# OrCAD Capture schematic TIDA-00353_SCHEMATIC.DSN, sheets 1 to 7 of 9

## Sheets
1 PAGE6 CLOCK_TRANSFORMERS: size B; title: ADC16DX370_LM97937EVM; rev: A; note: CLOCK_TRANSFORMERS
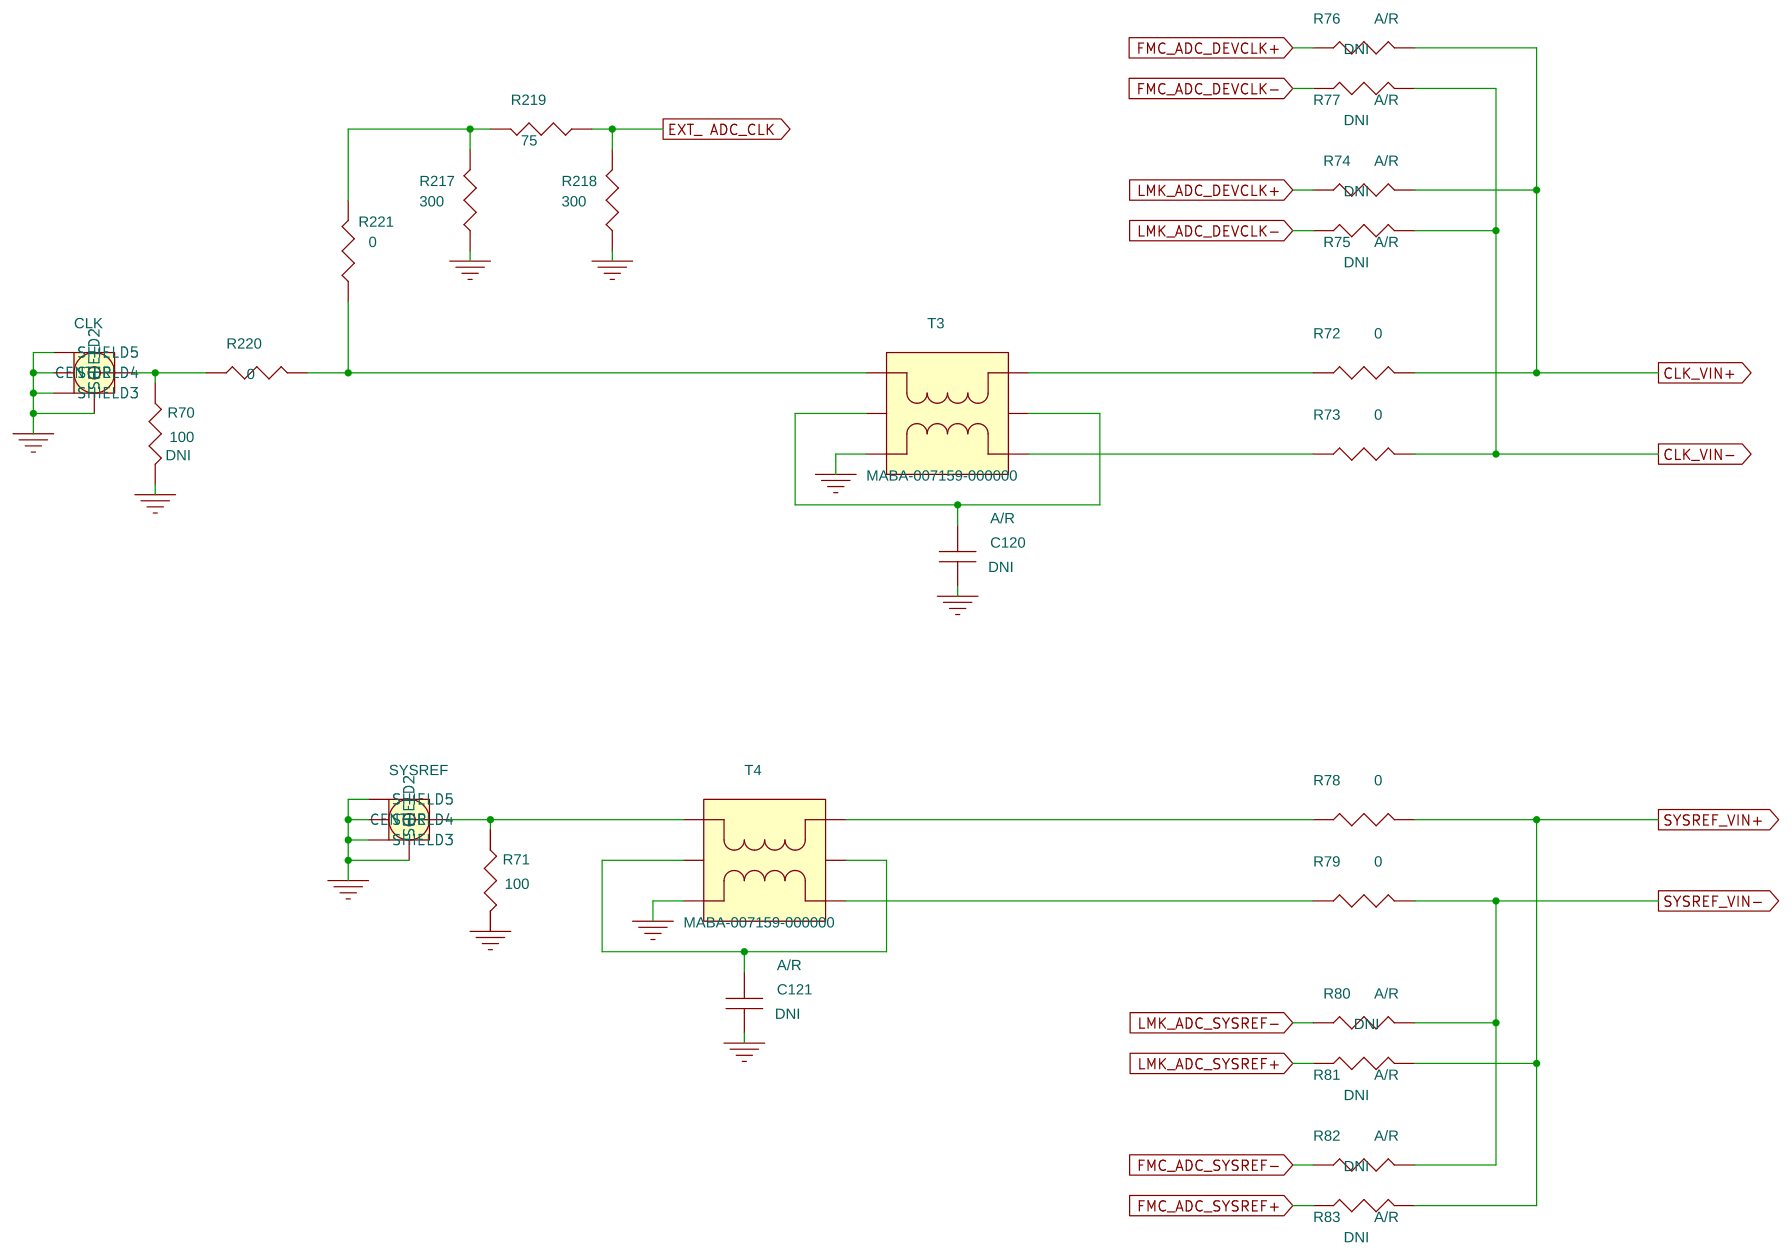
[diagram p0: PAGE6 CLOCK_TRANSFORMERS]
2 PAGE3 BPF: size B; note: BANDPASS_FILTERS
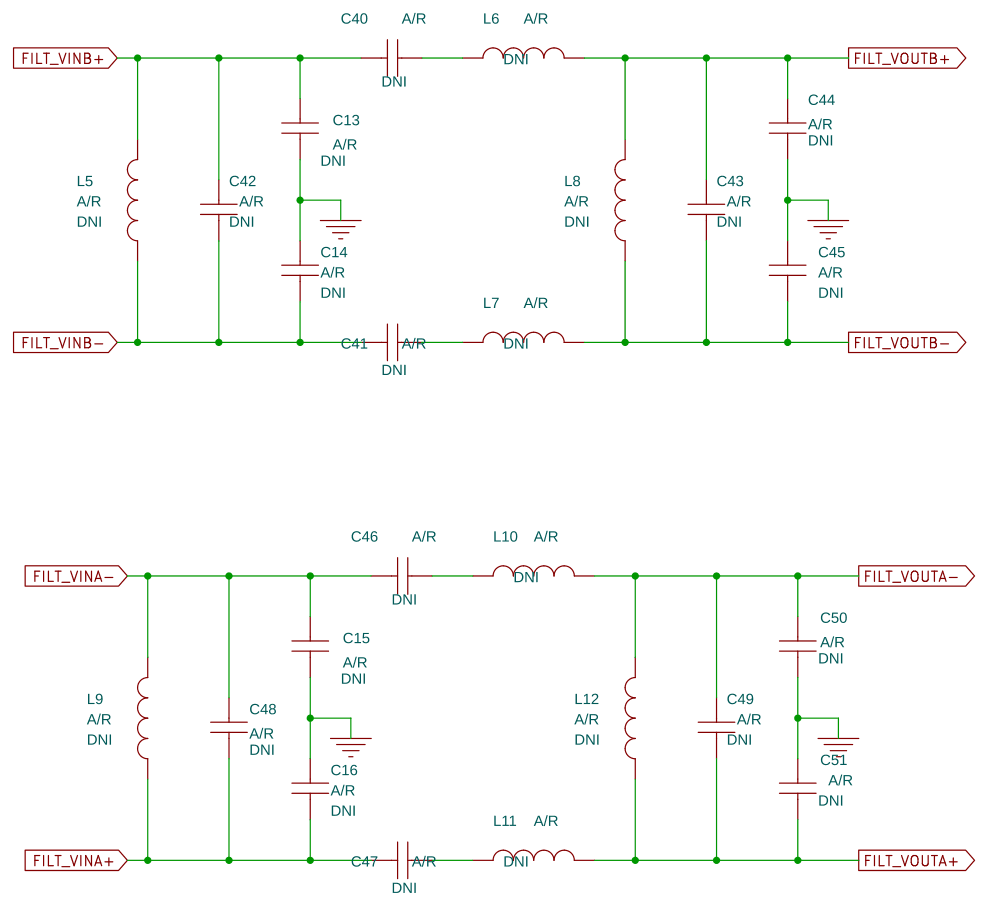
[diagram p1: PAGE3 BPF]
3 PAGE1 INPUT_TRANSFORMERS: size B
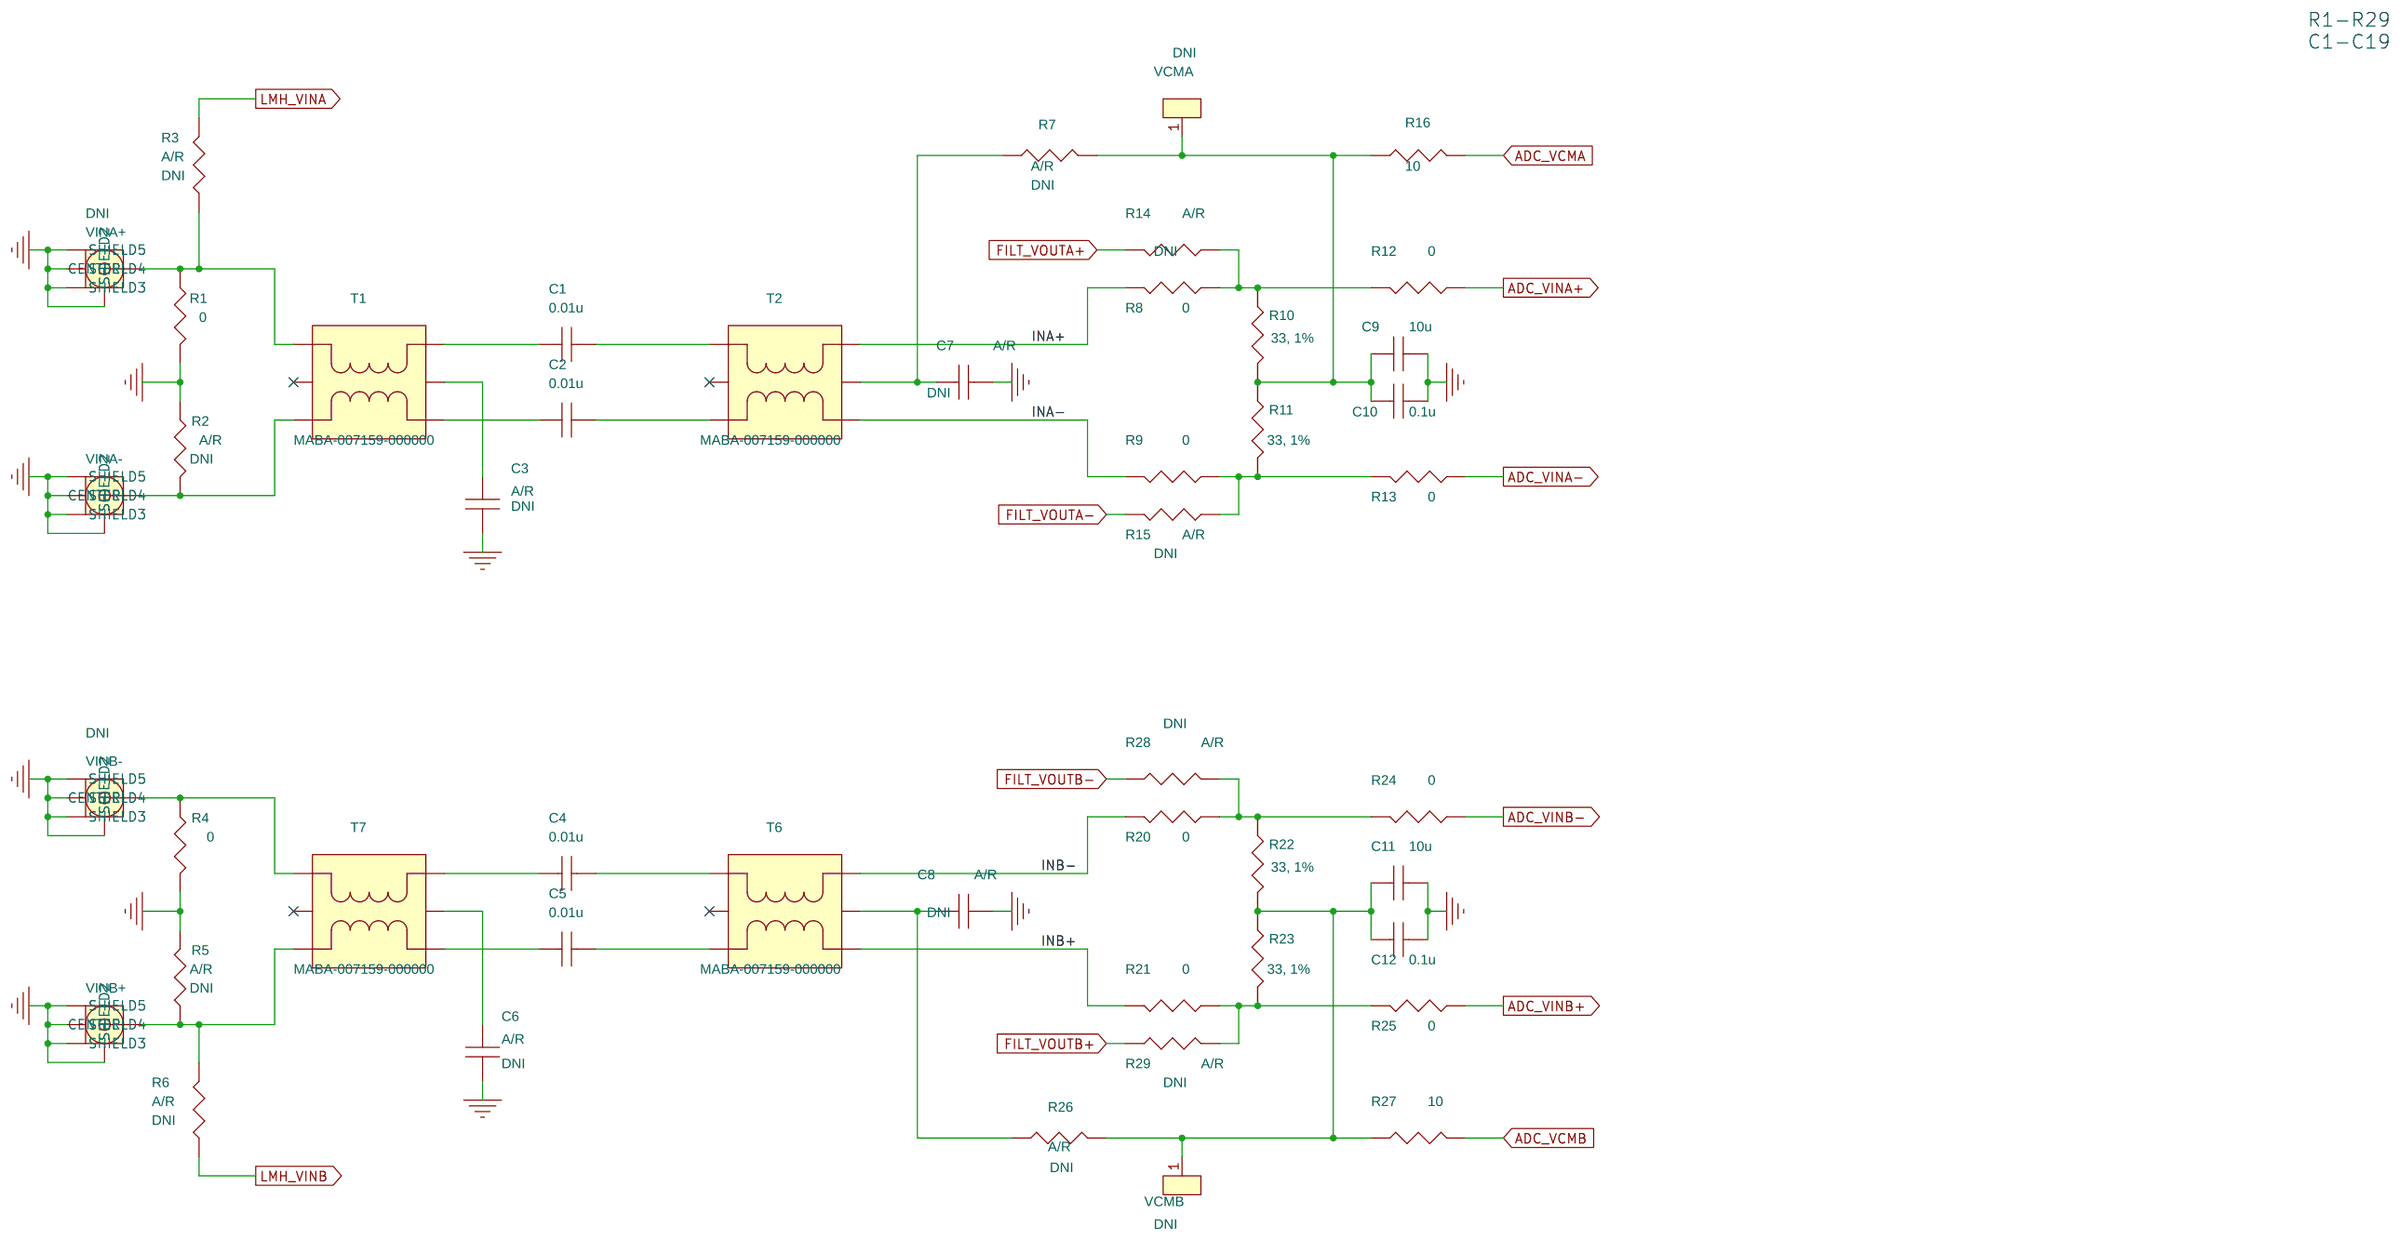
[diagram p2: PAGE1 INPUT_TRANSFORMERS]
4 PAGE2 LMH: size B; note: LMH
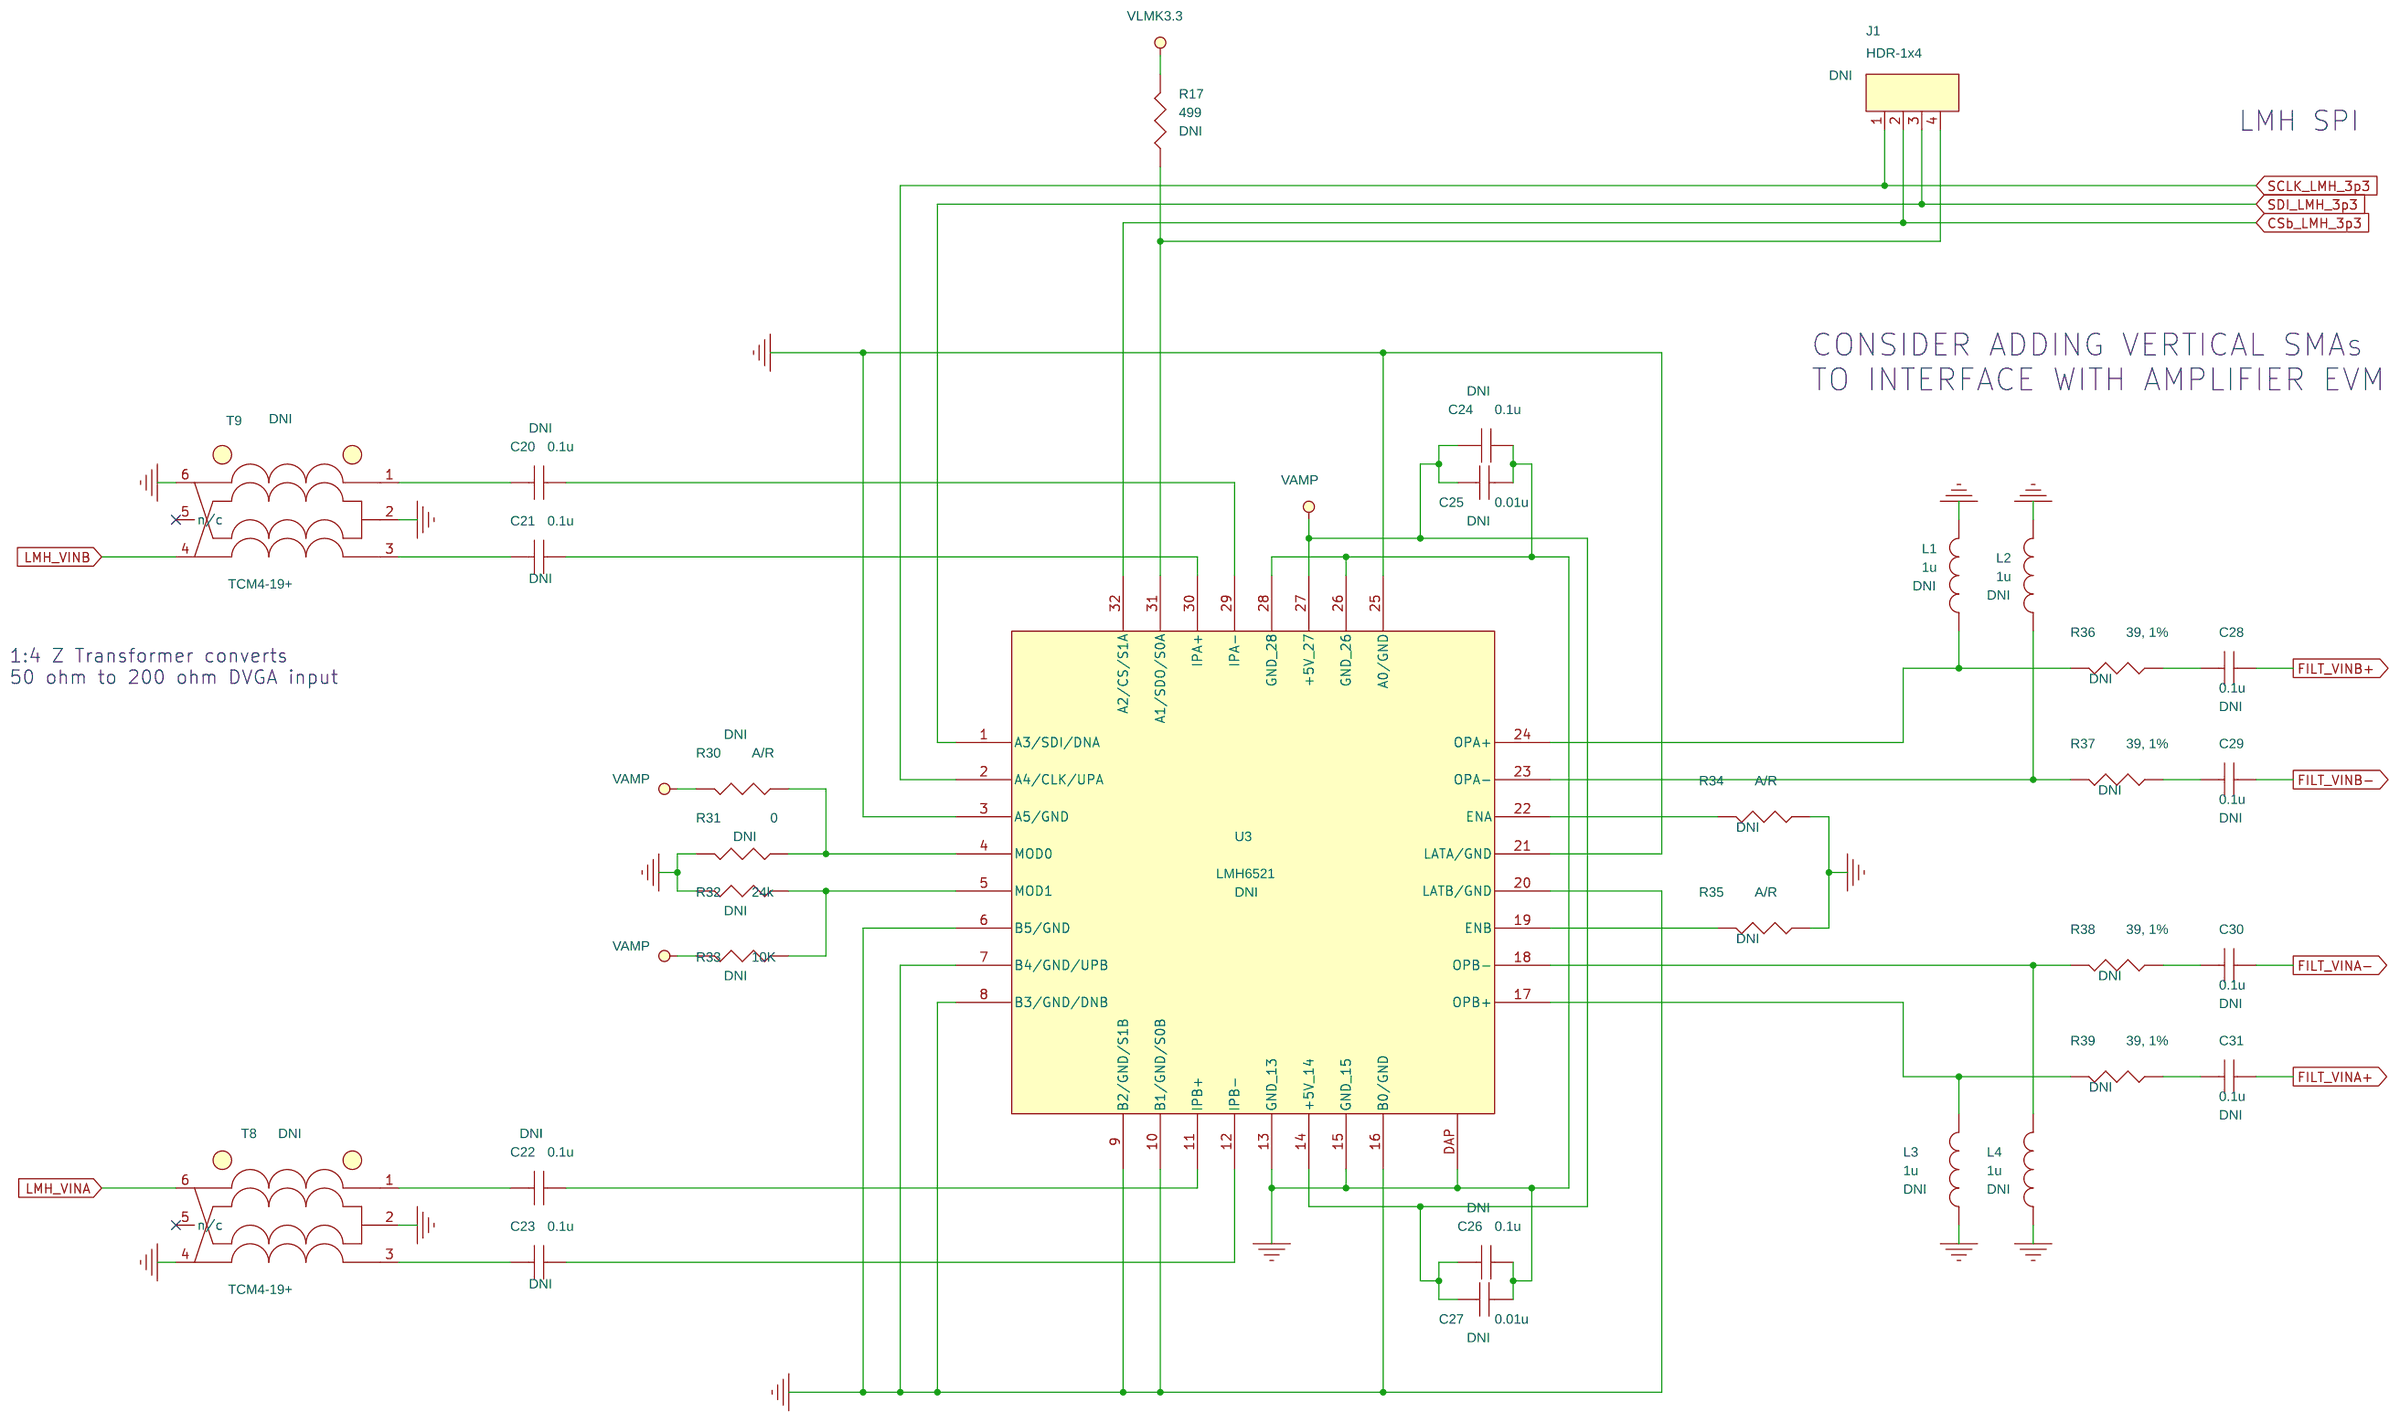
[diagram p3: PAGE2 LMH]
5 PAGE9 POWER: size B; note: POWER
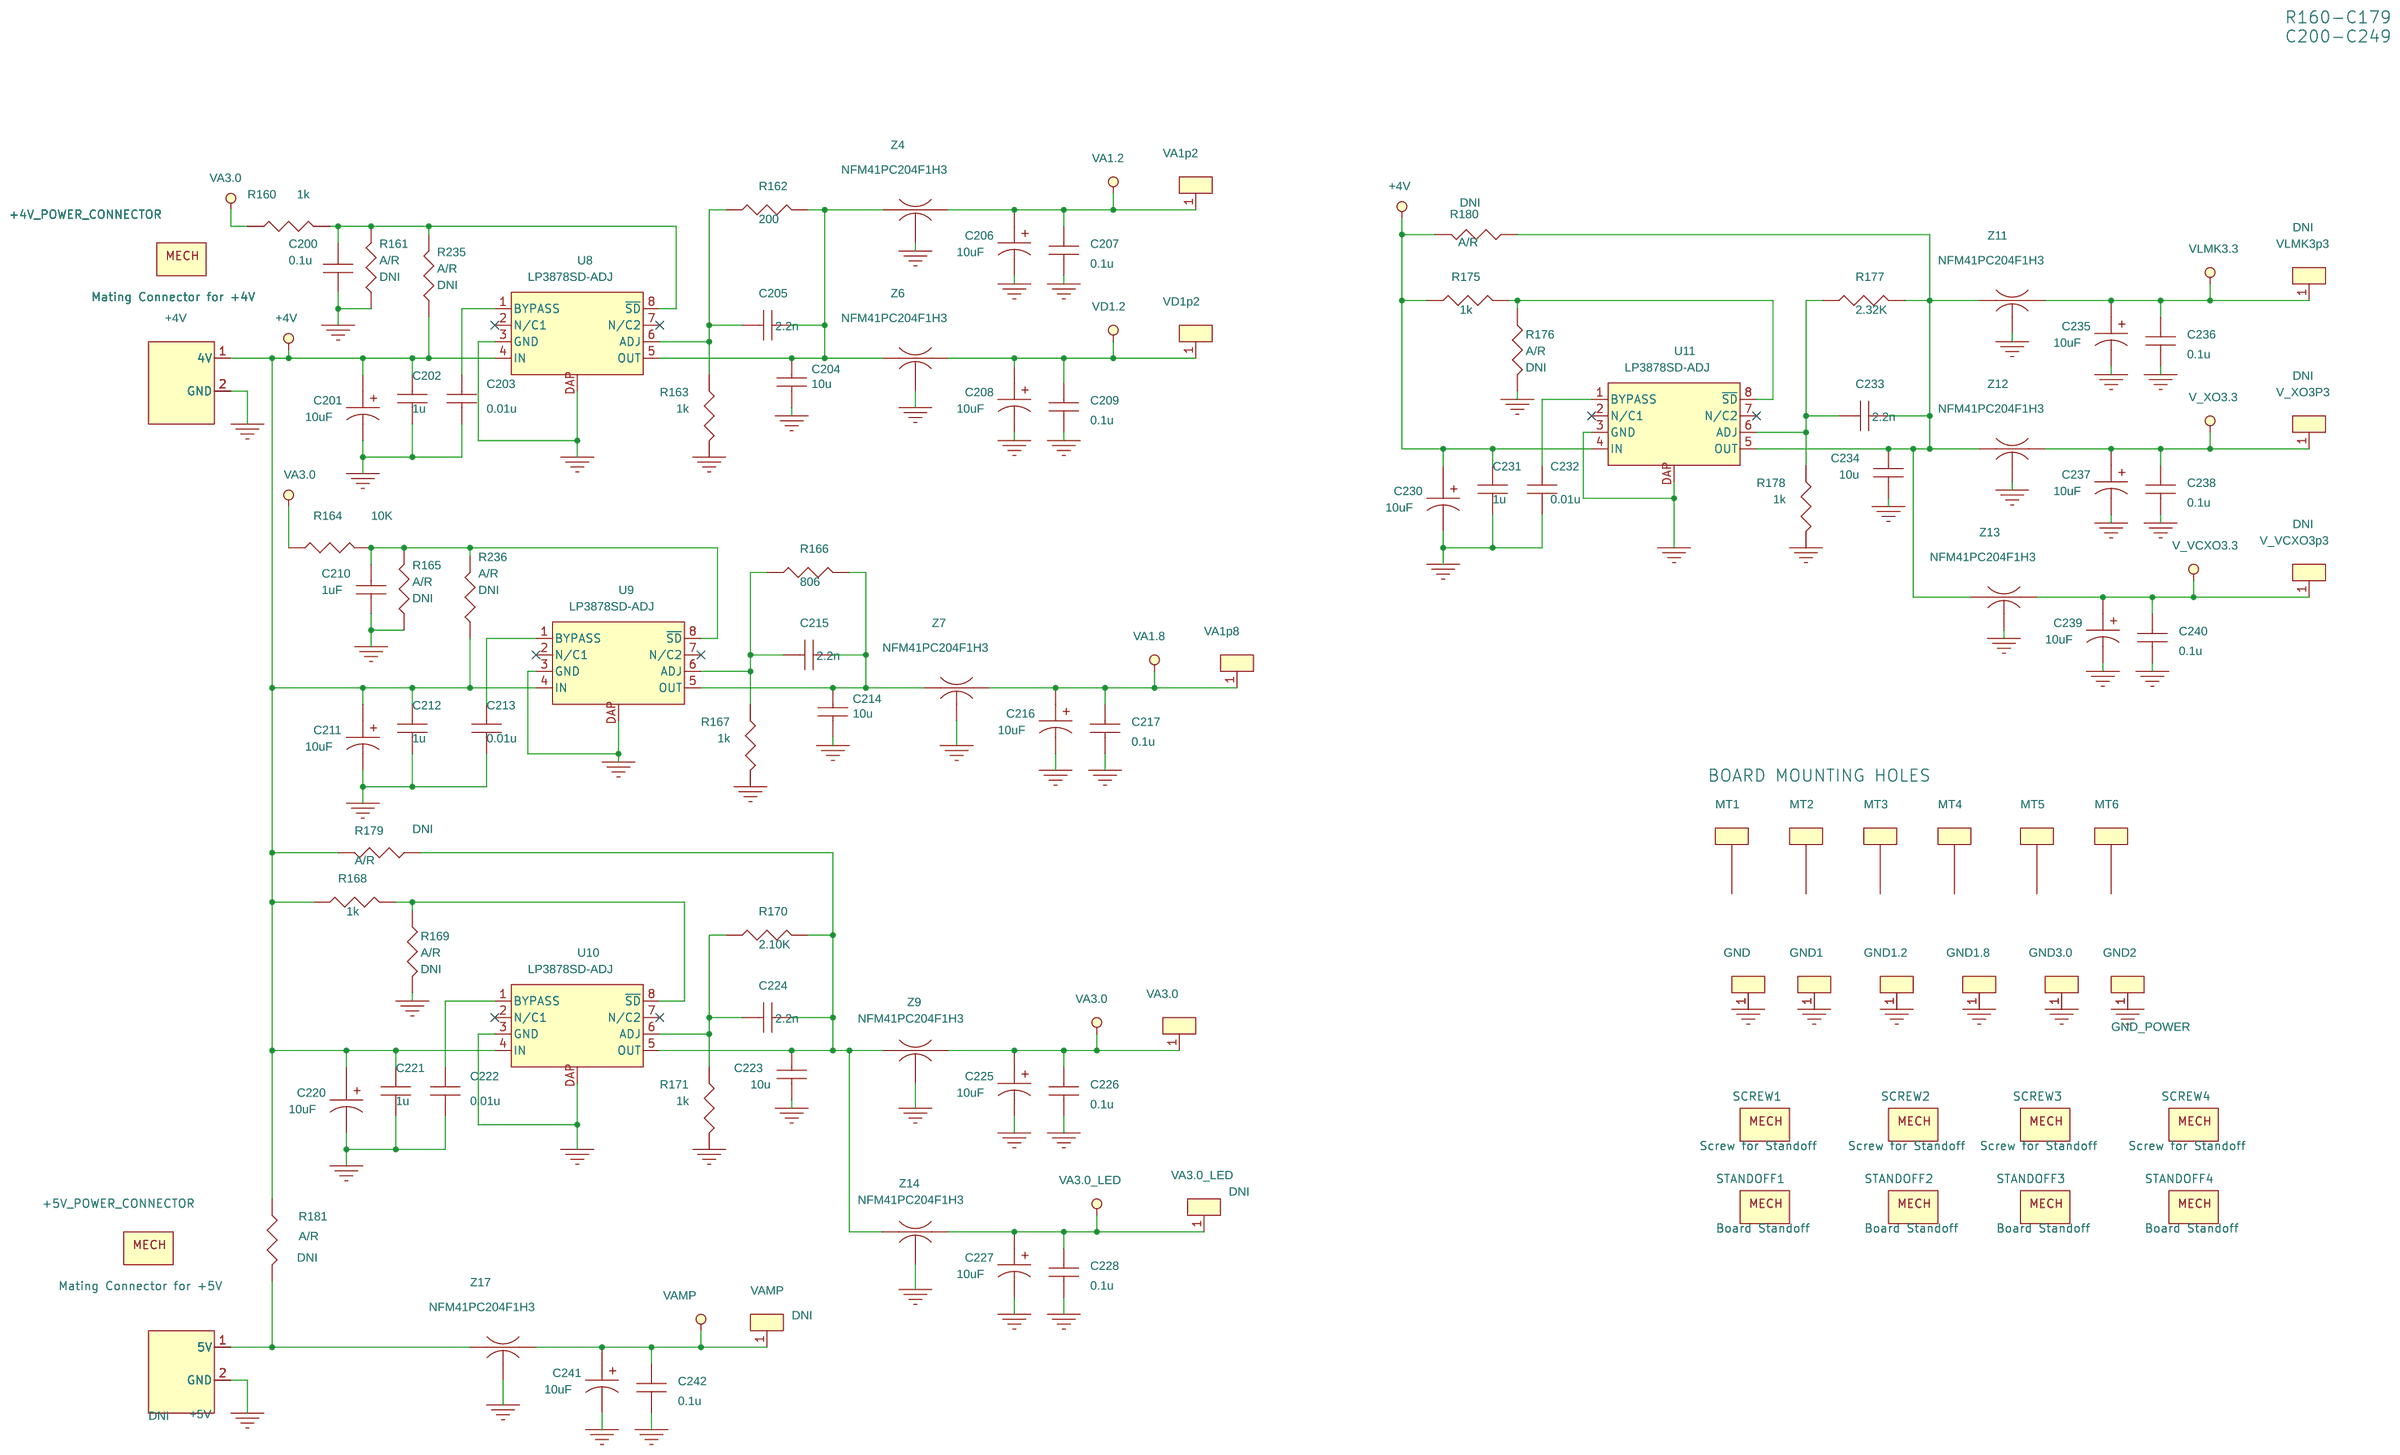
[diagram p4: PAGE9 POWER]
6 PAGE8 INTERFACE: size B; note: INTERFACE
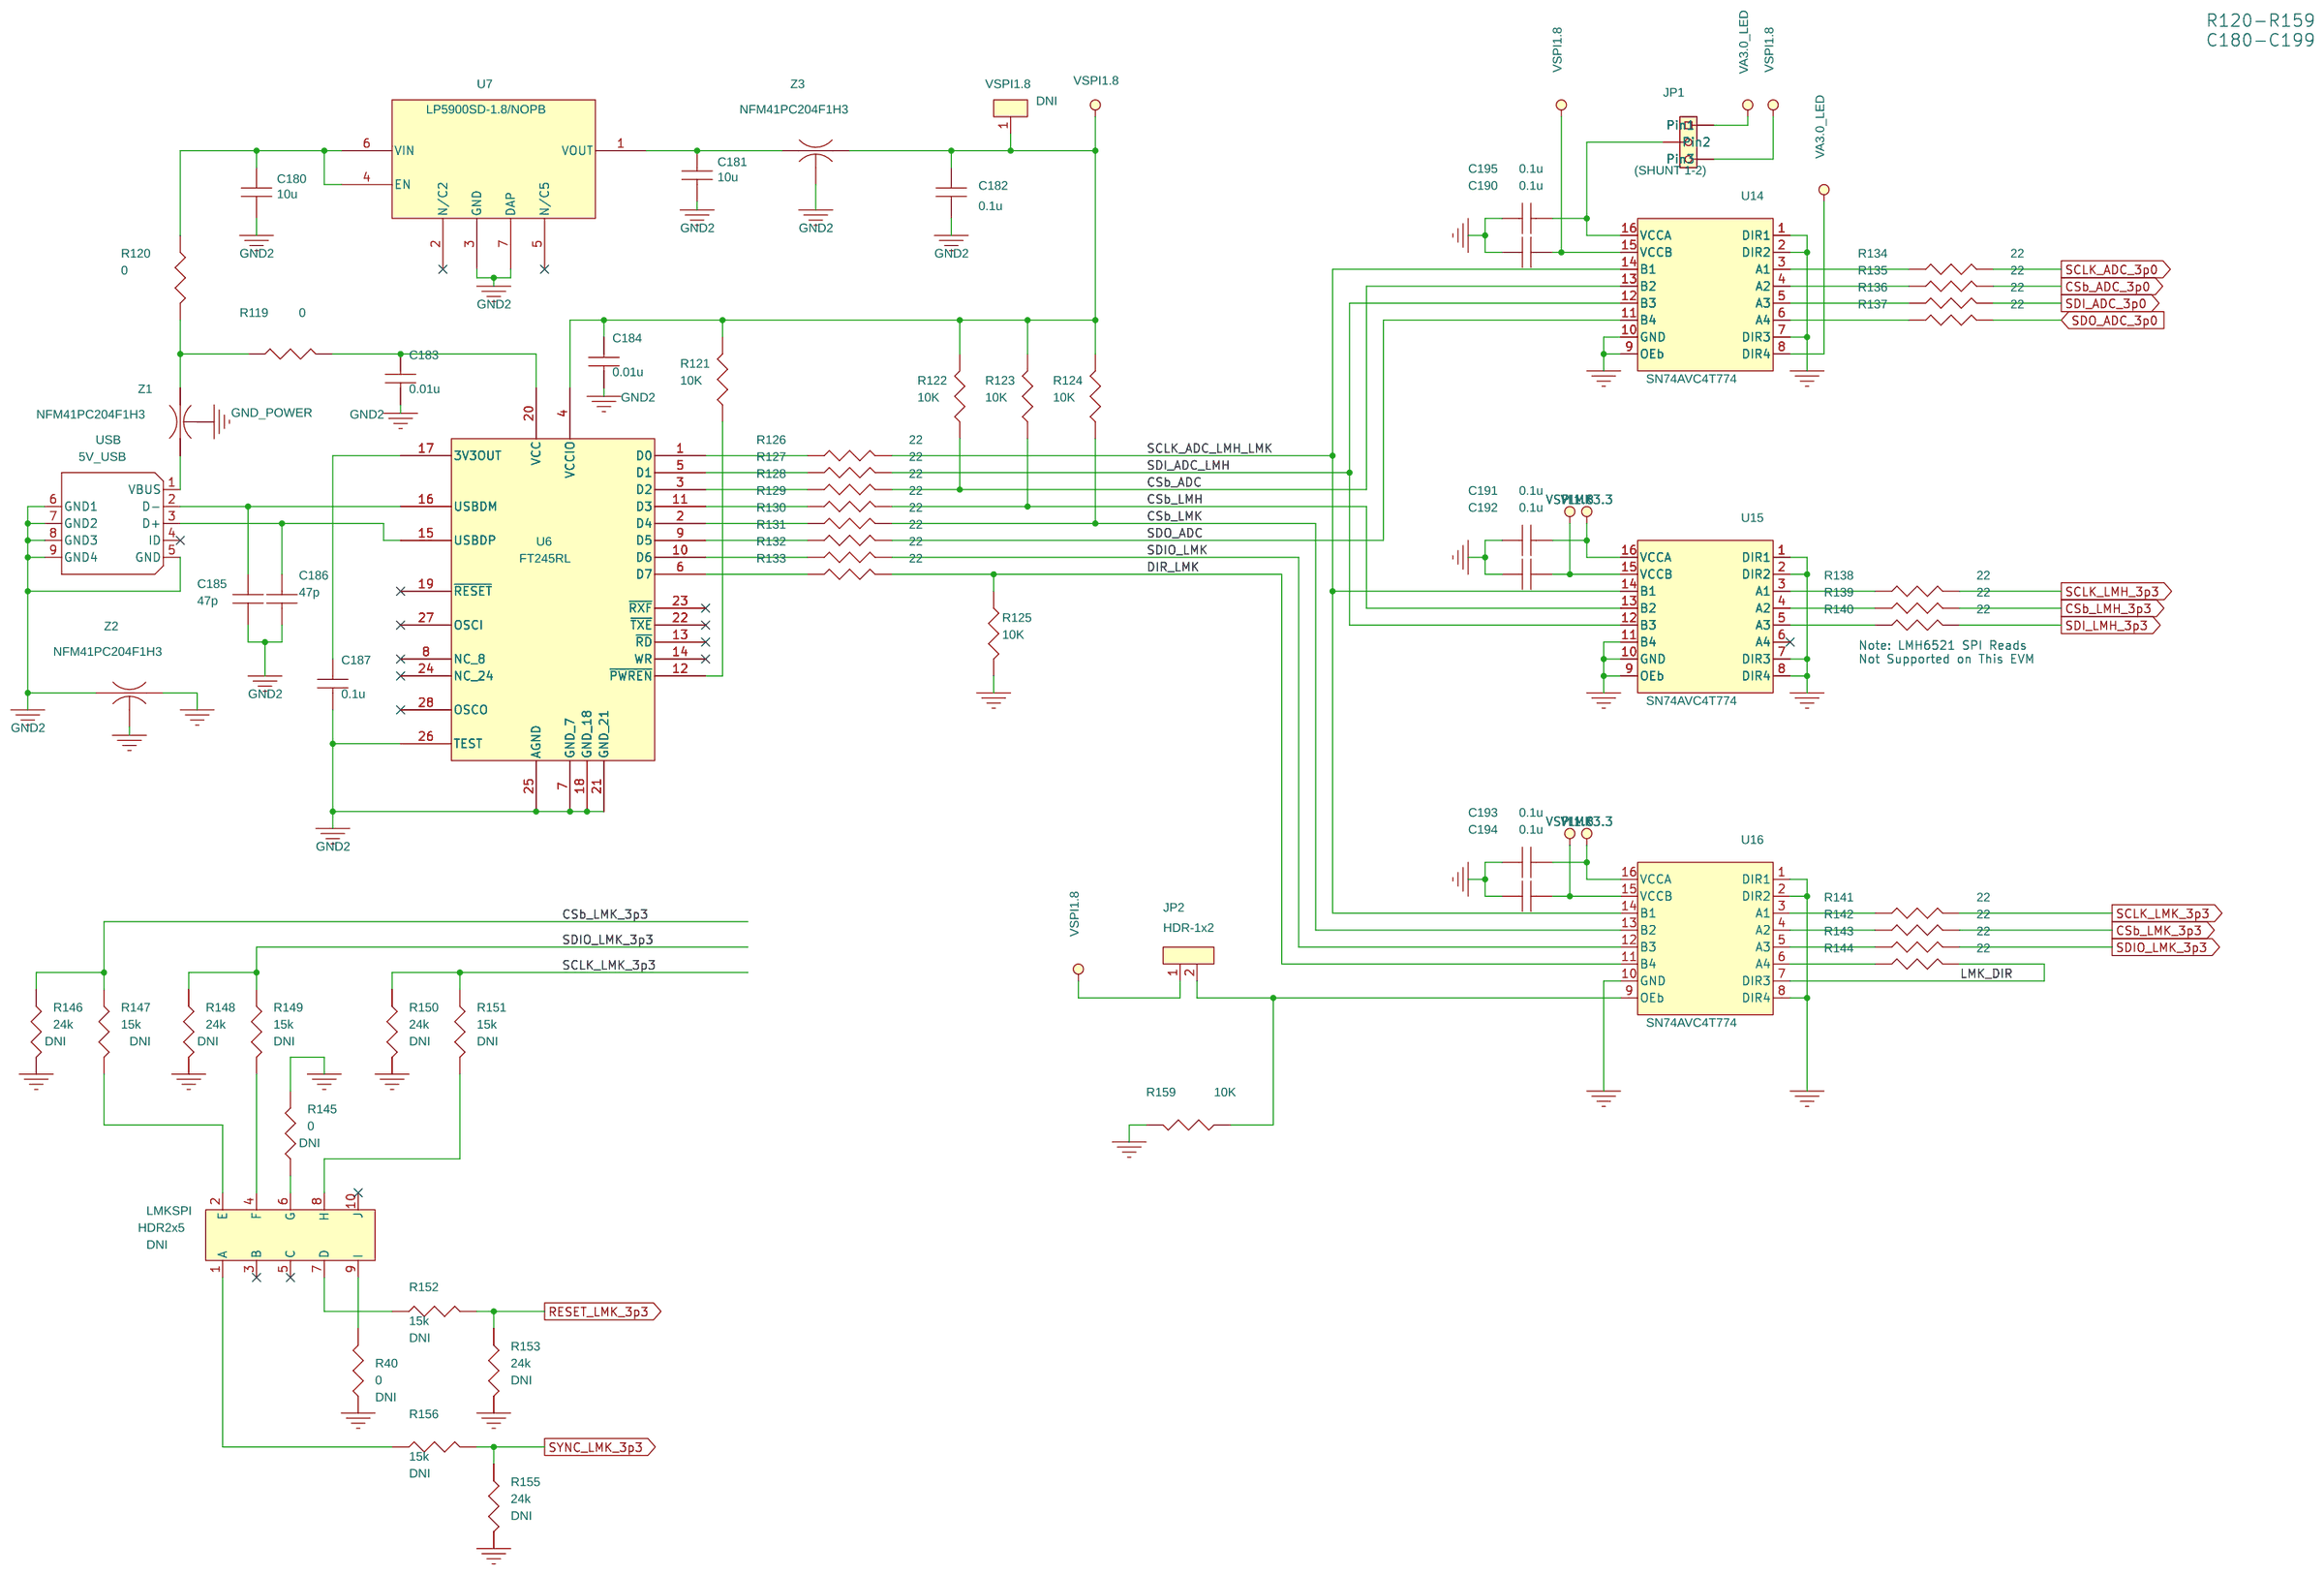
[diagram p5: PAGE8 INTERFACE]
7 PAGE5 FMC: size B; note: FMC
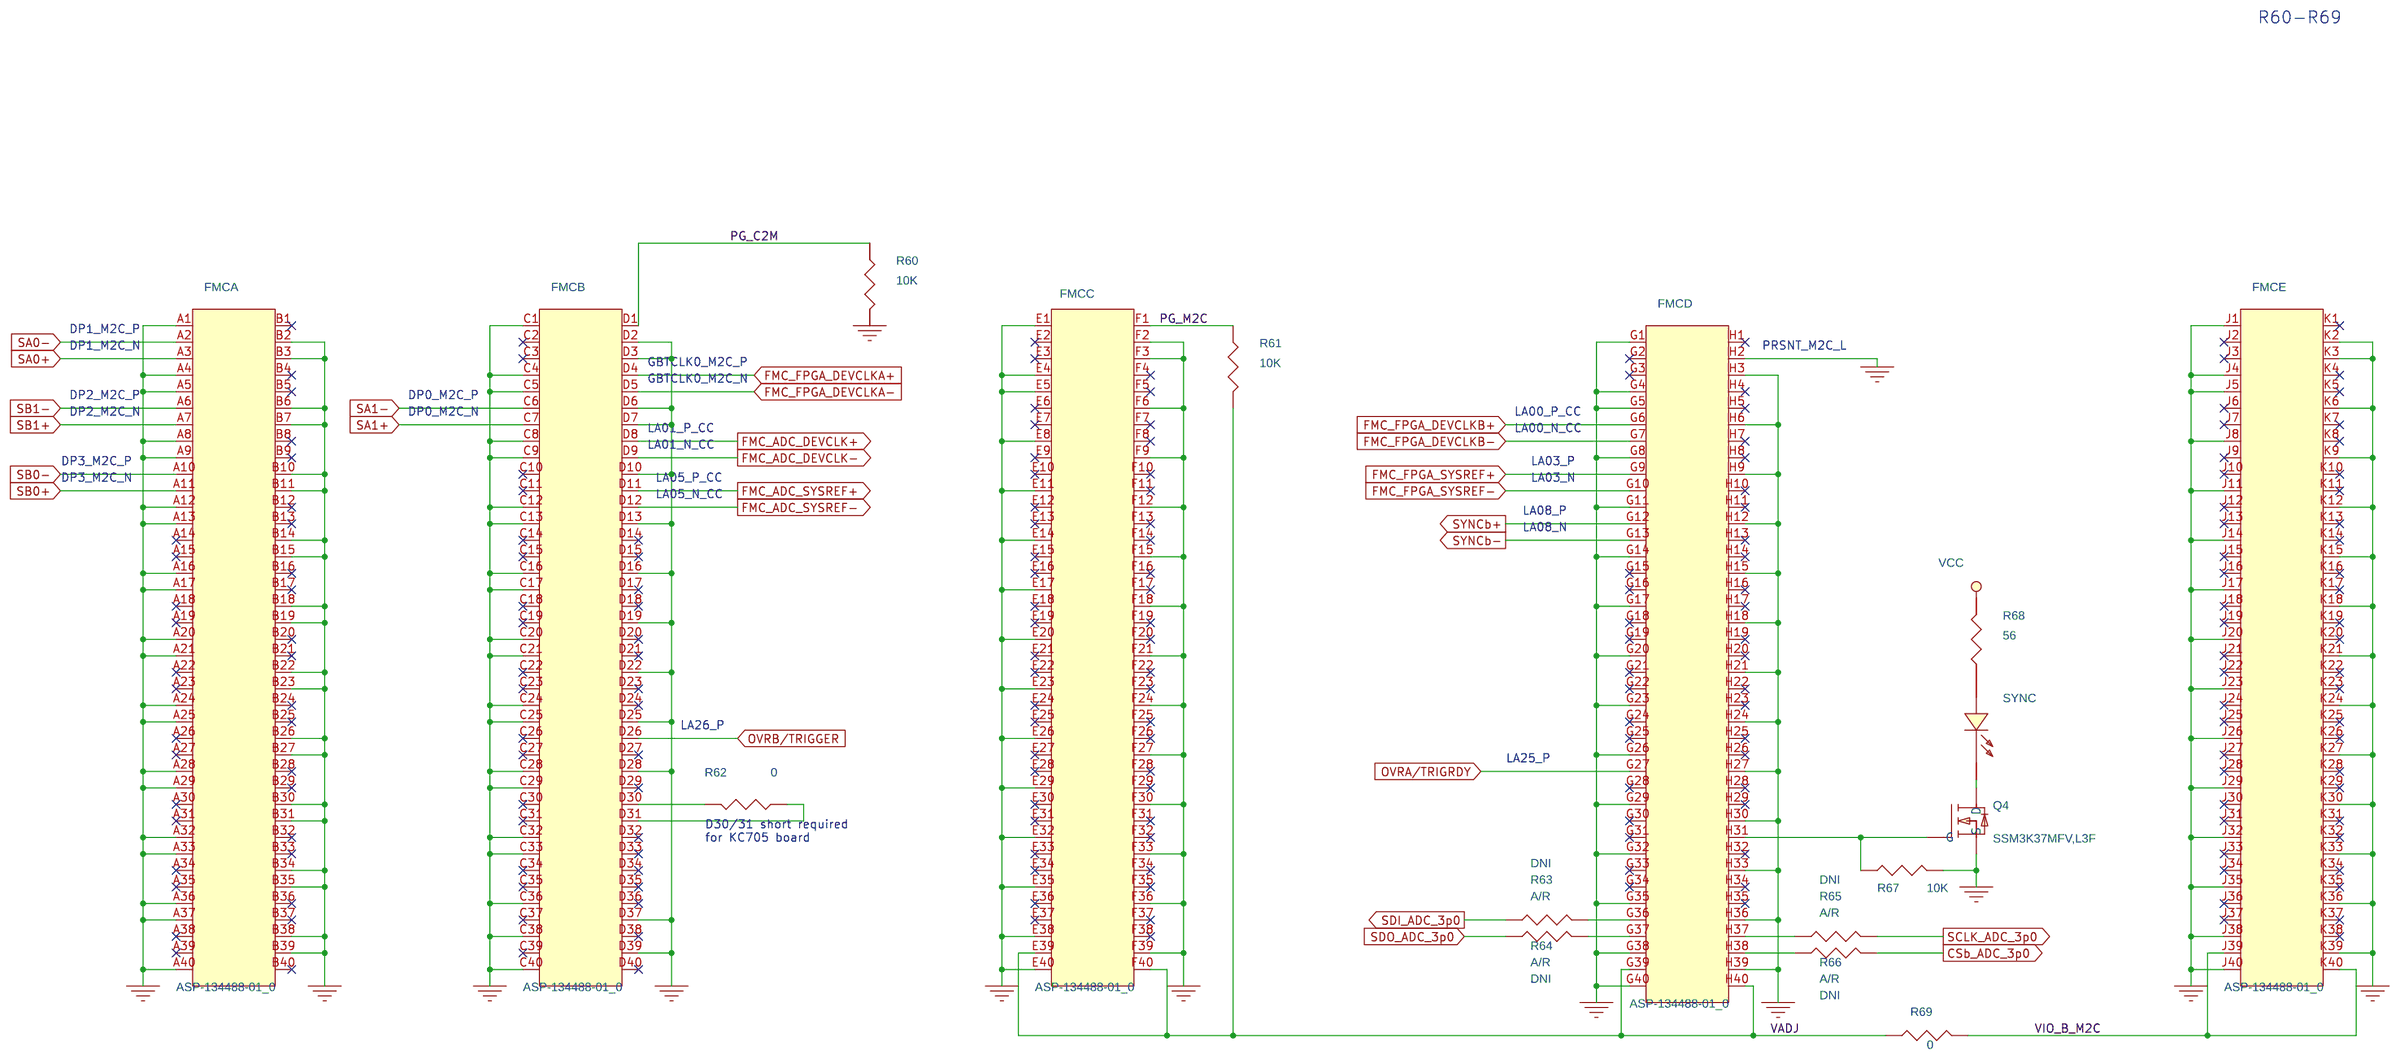
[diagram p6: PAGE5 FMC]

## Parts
sheet PAGE1 INPUT_TRANSFORMERS
C1  0.01u  [C0402_NO_SS]
C2  0.01u  [C0402_NO_SS]
C3  A/R  [C0402_NO_SS]
C4  0.01u  [C0402_NO_SS]
C5  0.01u  [C0402_NO_SS]
C6  A/R  [C0402_NO_SS]
C7  A/R  [C0402_NO_SS]
C8  A/R  [C0402_NO_SS]
C9  10u  [smd_size1206]
C10  0.1u  [C0402_NO_SS]
C11  10u  [smd_size1206]
C12  0.1u  [C0402_NO_SS]
R1  0  [C0402_NO_SS]
R2  A/R  [C0402_NO_SS]
R3  A/R  [C0402_NO_SS]
R4  0  [C0402_NO_SS]
R5  A/R  [C0402_NO_SS]
R6  A/R  [C0402_NO_SS]
R7  A/R  [C0402_NO_SS]
R8  0  [C0201_NO_SS]
R9  0  [C0201_NO_SS]
R10  33, 1%  [C0402_NO_SS]
R11  33, 1%  [C0402_NO_SS]
R12  0  [C0201_NO_SS]
R13  0  [C0201_NO_SS]
R14  A/R  [C0201_NO_SS]
R15  A/R  [C0201_NO_SS]
R16  10  [C0402_NO_SS]
R20  0  [C0201_NO_SS]
R21  0  [C0201_NO_SS]
R22  33, 1%  [C0402_NO_SS]
R23  33, 1%  [C0402_NO_SS]
R24  0  [C0201_NO_SS]
R25  0  [C0201_NO_SS]
R26  A/R  [C0402_NO_SS]
R27  10  [C0402_NO_SS]
R28  A/R  [C0201_NO_SS]
R29  A/R  [C0201_NO_SS]
T1  MABA-007159-000000  [MABA-007159-000000]
T2  MABA-007159-000000  [MABA-007159-000000]
T6  MABA-007159-000000  [MABA-007159-000000]
T7  MABA-007159-000000  [MABA-007159-000000]
VCMA  HDR-1x1_0  [tp_500x_50]
VCMB  HDR-1x1_0  [tp_500x_50]
VINA+  CLK_DIFF  [con_sma-edge]
VINA-  CLK_DIFF  [con_sma-edge]
VINB+  CLK_DIFF  [con_sma-edge]
VINB-  CLK_DIFF  [con_sma-edge]
sheet PAGE2 LMH
C20  0.1u  [smd_size0402]
C21  0.1u  [smd_size0402]
C22  0.1u  [smd_size0402]
C23  0.1u  [smd_size0402]
C24  0.1u  [C0402_NO_SS]
C25  0.01u  [C0402_NO_SS]
C26  0.1u  [C0402_NO_SS]
C27  0.01u  [C0402_NO_SS]
C28  0.1u  [C0402_NO_SS]
C29  0.1u  [C0402_NO_SS]
C30  0.1u  [C0402_NO_SS]
C31  0.1u  [C0402_NO_SS]
J1  HDR-1x4  [blkcon_4x1]
L1  1u  [coilcraft_size0603ls]
L2  1u  [coilcraft_size0603ls]
L3  1u  [coilcraft_size0603ls]
L4  1u  [coilcraft_size0603ls]
R17  499  [C0402_NO_SS]
R30  A/R  [C0402_NO_SS]
R31  0  [C0402_NO_SS]
R32  24k  [C0402_NO_SS]
R33  10K  [C0402_NO_SS]
R34  A/R  [C0402_NO_SS]
R35  A/R  [C0402_NO_SS]
R36  39, 1%  [C0402_NO_SS]
R37  39, 1%  [C0402_NO_SS]
R38  39, 1%  [C0402_NO_SS]
R39  39, 1%  [C0402_NO_SS]
T8  TCM4-19+  [db714]
T9  TCM4-19+  [db714]
U3  LMH6521  [32LLP_SQA32A]
sheet PAGE3 BPF
C13  A/R  [C0402_NO_SS]
C14  A/R  [C0402_NO_SS]
C15  A/R  [C0402_NO_SS]
C16  A/R  [C0402_NO_SS]
C40  A/R  [C0402_NO_SS]
C41  A/R  [C0402_NO_SS]
C42  A/R  [C0402_NO_SS]
C43  A/R  [C0402_NO_SS]
C44  A/R  [C0402_NO_SS]
C45  A/R  [C0402_NO_SS]
C46  A/R  [C0402_NO_SS]
C47  A/R  [C0402_NO_SS]
C48  A/R  [C0402_NO_SS]
C49  A/R  [C0402_NO_SS]
C50  A/R  [C0402_NO_SS]
C51  A/R  [C0402_NO_SS]
L5  A/R  [coilcraft_size0402hp]
L6  A/R  [coilcraft_size0603cs]
L7  A/R  [coilcraft_size0603cs]
L8  A/R  [coilcraft_size0402hp]
L9  A/R  [coilcraft_size0402hp]
L10  A/R  [coilcraft_size0603cs]
L11  A/R  [coilcraft_size0603cs]
L12  A/R  [coilcraft_size0402hp]
sheet PAGE5 FMC
FMC  ASP-134488-01_0  [conn_SEAM_040]  (sections A,B,C,D,E)
Q4  SSM3K37MFV,L3F  [sot-723]
R60  10K  [C0402_NO_SS]
R61  10K  [C0402_NO_SS]
R62  0  [C0402_NO_SS]
R63  A/R  [C0402_NO_SS]
R64  A/R  [C0402_NO_SS]
R65  A/R  [C0402_NO_SS]
R66  A/R  [C0402_NO_SS]
R67  10K  [C0402_NO_SS]
R68  56  [smd_size0402]
R69  0  [0603]
SYNC  LED  [LED_0805]
sheet PAGE6 CLOCK_TRANSFORMERS
C120  A/R  [smd_size0402]
C121  A/R  [smd_size0402]
CLK  CLK_DIFF  [con_sma-edge]
R70  100  [C0402_NO_SS]
R71  100  [C0402_NO_SS]
R72  0  [C0402_NO_SS]
R73  0  [C0402_NO_SS]
R74  A/R  [C0402_NO_SS]
R75  A/R  [C0402_NO_SS]
R76  A/R  [C0402_NO_SS]
R77  A/R  [C0402_NO_SS]
R78  0  [C0402_NO_SS]
R79  0  [C0402_NO_SS]
R80  A/R  [C0402_NO_SS]
R81  A/R  [C0402_NO_SS]
R82  A/R  [C0402_NO_SS]
R83  A/R  [C0402_NO_SS]
R217  300  [0402]
R218  300  [0402]
R219  75  [0402]
R220  0  [C0402_NO_SS]
R221  0  [C0402_NO_SS]
SYSREF  CLK_DIFF  [con_sma-edge]
T3  MABA-007159-000000  [MABA-007159-000000]
T4  MABA-007159-000000  [MABA-007159-000000]
sheet PAGE8 INTERFACE
C180  10u  [smd_size1206]
C181  10u  [smd_size1206]
C182  0.1u  [0603]
C183  0.01u  [C0402_NO_SS]
C184  0.01u  [C0402_NO_SS]
C185  47p  [C0402_NO_SS]
C186  47p  [C0402_NO_SS]
C187  0.1u  [C0402_NO_SS]
C190  0.1u  [smd_size0402]
C191  0.1u  [smd_size0402]
C192  0.1u  [smd_size0402]
C193  0.1u  [smd_size0402]
C194  0.1u  [smd_size0402]
C195  0.1u  [smd_size0402]
JP1  Jumper_1x3_100_430L  [HDR_THVT_1x3_100_M]
JP2  HDR-1x2  [blkcon_2x1]
LMKSPI  HDR2x5  [blkcon_5x2]
R40  0  [C0402_NO_SS]
R119  0  [0603]
R120  0  [0603]
R121  10K  [C0402_NO_SS]
R122  10K  [C0402_NO_SS]
R123  10K  [C0402_NO_SS]
R124  10K  [C0402_NO_SS]
R125  10K  [C0402_NO_SS]
R126  22  [C0402_NO_SS]
R127  22  [C0402_NO_SS]
R128  22  [C0402_NO_SS]
R129  22  [C0402_NO_SS]
R130  22  [C0402_NO_SS]
R131  22  [C0402_NO_SS]
R132  22  [C0402_NO_SS]
R133  22  [C0402_NO_SS]
R134  22  [C0402_NO_SS]
R135  22  [C0402_NO_SS]
R136  22  [C0402_NO_SS]
R137  22  [C0402_NO_SS]
R138  22  [C0402_NO_SS]
R139  22  [C0402_NO_SS]
R140  22  [C0402_NO_SS]
R141  22  [C0402_NO_SS]
R142  22  [C0402_NO_SS]
R143  22  [C0402_NO_SS]
R144  22  [C0402_NO_SS]
R145  0  [C0402_NO_SS]
R146  24k  [smd_size0402]
R147  15k  [smd_size0402]
R148  24k  [smd_size0402]
R149  15k  [smd_size0402]
R150  24k  [smd_size0402]
R151  15k  [smd_size0402]
R152  15k  [smd_size0402]
R153  24k  [smd_size0402]
R155  24k  [smd_size0402]
R156  15k  [smd_size0402]
R159  10K  [C0402_NO_SS]
U6  FT245RL  [FT245RL]
U7  LP5900SD-1.8/NOPB  [sc-mkt-sdb06a_6llp]
U14  SN74AVC4T774  [tssop16_pw]
U15  SN74AVC4T774  [tssop16_pw]
U16  SN74AVC4T774  [tssop16_pw]
USB  USB_MINI_AB_MNE20-5G5P10  [CON_SMRT_USBMNE20_F]
VSPI1.8  TP, RED  [tp_500x_50]
Z1  NFM41PC204F1H3  [nfm41p]
Z2  NFM41PC204F1H3  [nfm41p]
Z3  NFM41PC204F1H3  [nfm41p]
Z_SH-H12  SHUNT-HEADER
sheet PAGE9 POWER
+4V  Terminal_Block2  [mstba_ra_200_2]
+4V_POWER_CONNECTOR  Mating Connector for +4V
+5V  Terminal_Block2  [mstba_ra_200_2]
+5V_POWER_CONNECTOR  Mating Connector for +5V
C200  0.1u  [C0402_NO_SS]
C201  10uF  [cap_a-case]
C202  1u  [smd_size1206]
C203  0.01u  [C0402_NO_SS]
C204  10u  [smd_size1206]
C205  2.2n  [smd_size0603]
C206  10uF  [cap_a-case]
C207  0.1u  [0603]
C208  10uF  [cap_a-case]
C209  0.1u  [0603]
C210  1uF  [C0402_NO_SS]
C211  10uF  [cap_a-case]
C212  1u  [smd_size1206]
C213  0.01u  [C0402_NO_SS]
C214  10u  [smd_size1206]
C215  2.2n  [smd_size0603]
C216  10uF  [cap_a-case]
C217  0.1u  [0603]
C220  10uF  [cap_a-case]
C221  1u  [smd_size1206]
C222  0.01u  [C0402_NO_SS]
C223  10u  [smd_size1206]
C224  2.2n  [smd_size0603]
C225  10uF  [cap_a-case]
C226  0.1u  [0603]
C227  10uF  [cap_a-case]
C228  0.1u  [0603]
C230  10uF  [cap_a-case]
C231  1u  [smd_size1206]
C232  0.01u  [C0402_NO_SS]
C233  2.2n  [smd_size0603]
C234  10u  [smd_size1206]
C235  10uF  [cap_a-case]
C236  0.1u  [0603]
C237  10uF  [cap_a-case]
C238  0.1u  [0603]
C239  10uF  [cap_a-case]
C240  0.1u  [0603]
C241  10uF  [cap_a-case]
C242  0.1u  [0603]
GND  TP, BLACK  [tp_500x_50]
GND1  TP, BLACK  [tp_500x_50]
GND1.2  TP, BLACK  [tp_500x_50]
GND1.8  TP, BLACK  [tp_500x_50]
GND2  TP, BLACK  [tp_500x_50]
GND3.0  TP, BLACK  [tp_500x_50]
MT1  TP  [VIA85D55]
MT2  TP  [VIA85D55]
MT3  TP  [VIA85D55]
MT4  TP  [VIA85D55]
MT5  TP  [VIA85D55]
MT6  TP  [VIA85D55]
R160  1k  [smd_size0402]
R161  A/R  [smd_size0402]
R162  200  [smd_size0402]
R163  1k  [smd_size0402]
R164  10K  [smd_size0402]
R165  A/R  [smd_size0402]
R166  806  [smd_size0402]
R167  1k  [smd_size0402]
R168  1k  [smd_size0402]
R169  A/R  [smd_size0402]
R170  2.10K  [smd_size0402]
R171  1k  [smd_size0402]
R175  1k  [smd_size0402]
R176  A/R  [smd_size0402]
R177  2.32K  [smd_size0402]
R178  1k  [smd_size0402]
R179  A/R  [0603]
R180  A/R  [0603]
R181  A/R  [0603]
R235  A/R  [smd_size0402]
R236  A/R  [smd_size0402]
SCREW1  Screw for Standoff
SCREW2  Screw for Standoff
SCREW3  Screw for Standoff
SCREW4  Screw for Standoff
STANDOFF1  Board Standoff
STANDOFF2  Board Standoff
STANDOFF3  Board Standoff
STANDOFF4  Board Standoff
U8  LP3878SD-ADJ  [sc-mkt-sdc08a_llp]
U9  LP3878SD-ADJ  [sc-mkt-sdc08a_llp]
U10  LP3878SD-ADJ  [sc-mkt-sdc08a_llp]
U11  LP3878SD-ADJ  [sc-mkt-sdc08a_llp]
V_VCXO3p3  TP, RED  [tp_500x_50]
V_XO3P3  TP, RED  [tp_500x_50]
VA1p2  TP, RED  [tp_500x_50]
VA1p8  TP, RED  [tp_500x_50]
VA3.0  TP, RED  [tp_500x_50]
VA3.0_LED  TP, RED  [tp_500x_50]
VAMP  TP, RED  [tp_500x_50]
VD1p2  TP, RED  [tp_500x_50]
VLMK3p3  TP, RED  [tp_500x_50]
Z4  NFM41PC204F1H3  [nfm41p]
Z6  NFM41PC204F1H3  [nfm41p]
Z7  NFM41PC204F1H3  [nfm41p]
Z9  NFM41PC204F1H3  [nfm41p]
Z11  NFM41PC204F1H3  [nfm41p]
Z12  NFM41PC204F1H3  [nfm41p]
Z13  NFM41PC204F1H3  [nfm41p]
Z14  NFM41PC204F1H3  [nfm41p]
Z17  NFM41PC204F1H3  [nfm41p]

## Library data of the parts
C1 C2 C4 C5 = Capacitor_4: Distributed by: Digikey; Distributor Part #: 445-1260-1-ND; Manufactured by: TDK Corporation; Part Description: CAP CER 10000PF 25V 10% X7R 0402; Part Number: C1005X7R1E103K050BB
C3 C6 = Capacitor_4: Note: DNI
C7 C8 = Cap_1: Note: DNI
C9 C11 C180 C181 C204 C214 C223 C234 = Capacitor_0: Distributed by: Digikey; Distributor Part #: 490-3373-1-ND; MFR's P/N: GRM31CR61E106KA12L; Manufactured by: Murata; Part Description: CAP CER 10UF 25V X5R 1206; Part Number: GRM31CR61E106KA12L
C10 C12 C187 C200 = Cap_1: Distributed by: Digikey; Distributor Part #: 490-5415-1-ND; Manufactured by: Murata Electronics North America; Part Description: CAP CER .1UF 16V X5R 0402; Part Number: GRM155R61C104KA88D
R1 = Resistor_3: MFR's P/N: ERJ-2GE0R00X; Manufactured by: Panasonic; Part Description: RES 0.0 OHM 1/10W JUMP 0402 SMD; Part Number: ERJ-2GE0R00X
R2 = Resistor_3: Distributed by: Digikey; Distributor Part #: P0.0JCT-ND; Note: DNI
R3 R5-R7 R14 R15 R26 R28-R30 R34 R35 R63-R66 R74-R77 R80-R83 R169 R176 = Resistor_3: Note: DNI
R4 R62 R72 R73 R78 R79 = Resistor_3: Distributed by: Digikey; Distributor Part #: P0.0JCT-ND; MFR's P/N: ERJ-2GE0R00X; Manufactured by: Panasonic; Part Description: RES 0.0 OHM 1/10W JUMP 0402 SMD; Part Number: ERJ-2GE0R00X
R8 R9 R12 R13 R20 R21 R24 R25 = Resistor_3: Distributed by: Digikey; Distributor Part #: P0.0AGCT-ND; MFR's P/N: ERJ-1GE0R00C; Manufactured by: Panasonic; Part Description: RES 0.0 OHM 1/20W JUMP 0201 SMD; Part Number: ERJ-1GE0R00C
R10 R11 R22 R23 = Resistor_3: Distributed by: Digikey; Distributor Part #: P33.0LCT-ND; MFR's P/N: ERJ-2RKF33R0X; Manufactured by: Panasonic - ECG; Part Description: RES 33.0 OHM 1/10W 1% 0402 SMD; Part Number: ERJ-2RKF33R0X
R16 R27 = Resistor_3: Distributed by: Digikey; Distributor Part #: P10JCT-ND; Manufactured by: Panasonic; Part Description: RES 10 OHM 1/10W 5% 0402 SMD; Part Number: ERJ-2GEJ100X
T1-T4 T6 T7 = MABA-007159-000000: Distributed by: Mouser; Distributor Part #: 937-MABA007159000000; Manufactured by: M/A-COM Technology Solutions; Part Description: Transformers Audio & Signal 4.5-3000MHz IL 2dB Impedance Ratio 1:1
VCMA VCMB = HDR-1x1_2: Note: DNI
VINA+ VINB- = SMA_CONN_5: Distributed by: Digikey; Distributor Part #: J658-ND; MFR's P/N: 142-0701-851; Manufactured by: Johnson; Note: DNI; Part Description: CONN JACK END LAUNCH PC GOLD SMA; Part Number: 142-0701-851
CLK SYSREF VINA- VINB+ = SMA_CONN_5: Distributed by: Digikey; Distributor Part #: J658-ND; MFR's P/N: 142-0701-851; Manufactured by: Johnson; Part Description: CONN JACK END LAUNCH PC GOLD SMA; Part Number: 142-0701-851
C20-C23 C120 C121 = Capacitor_3: Distributed by: Digikey; Distributor Part #: 490-5415-1-ND; Manufactured by: Murata Electronics North America; Note: DNI; Part Description: CAP CER 0.1UF 16V 10% X5R 0402; Part Number: GRM155R61C104KA88D
C24 C26 C28-C31 = Capacitor_3: Distributed by: Digikey; Distributor Part #: 490-5415-1-ND; Manufactured by: Murata Electronics North America; Note: DNI; Part Description: CAP CER .1UF 16V X5R 0402; Part Number: GRM155R61C104KA88D
C25 C27 = Capacitor_4: Distributed by: Digikey; Distributor Part #: 445-1260-1-ND; Manufactured by: TDK Corporation; Note: DNI; Part Description: CAP CER 10000PF 25V 10% X7R 0402; Part Number: C1005X7R1E103K050BB
J1 = HDR-1x4_0: Note: DNI
L1-L4 = INDUCTOR: Distributed by: Coilcraft; Distributor Part #: 0603LS-102XJLB; Manufactured By: Coilcraft; Note: DNI; Part Description: Chip Inductors – 0603LS (1608); Part Number: 0603LS-102XJLB; size: 0603
R17 = Resistor_3: Distributed by: Digikey; Distributor Part #: ERJ-2RKF4990X; Manufactured by: Panasonic; Note: DNI; Part Description: RES 499 OHM 1/10W 1% 0402 SMD; Part Number: ERJ-2RKF4990X
R31 R40 R145 = Resistor_3: Distributed by: Digikey; Distributor Part #: P0.0JCT-ND; MFR's P/N: ERJ-2GE0R00X; Manufactured by: Panasonic; Note: DNI; Part Description: RES 0.0 OHM 1/10W JUMP 0402 SMD; Part Number: ERJ-2GE0R00X
R32 = Resistor_3: Distributed by: Digikey; Distributor Part #: P24KJCT-ND; MFR's P/N: ERJ-2GEJ243X; Manufactured by: Panasonic Electronic Components; Note: DNI; Part Description: RES 24K OHM 1/10W 5% 0402 SMD; Part Number: ERJ-2GEJ243X
R33 = Resistor_3: Distributed by: Digikey; Distributor Part #: 541-10.0KLCT-ND; Manufactured by: Vishay Dale; Note: DNI; Part Description: RES 10.0K OHM 1/16W 1% 0402 SMD; Part Number: CRCW040210K0FKED
R36 = Resistor_3: Distributed by: Digikey; Distributor Part #: P39.0LCT-ND; Manufactured by: Panasonic; Note: DNI; Part Description: RES 39.0 OHM 1/10W 1% 0402 SMD; Part Number: ERJ-2RKF39R0X
R37-R39 = Resistor_3: Distributed by: Digikey; Distributor Part #: P39.0LCT-ND; MFR's P/N: ERJ-2RKF39R0X; Manufactured by: Panasonic; Note: DNI; Part Description: RES 39.0 OHM 1/10W 1% 0402 SMD; Part Number: ERJ-2RKF39R0X
T8 T9 = TCM4-19+_0: Distributed by: Mini-Circuits; Manufactured by: Mini-Circuits; Note: DNI; Part Description: Surface Mount RF Transformer 50 Ohm 10 to 1900 MHz
U3 = LMH6517_4: Distributed by: Digikey; Distributor Part #: 296-35191-1-ND; MFR's P/N: LMH6521SQE/NOPB; Manufactured by: Texas Instruments; Note: DNI; Part Description: High Performance Dual DVGA; Part Number: LMH6521SQE/NOPB
C13-C16 C44 C45 C50 C51 = Capacitor_3: Note: DNI
C40 C41 C46 C47 = Capacitor_3: Distributed by: Digikey; Distributor Part #: 399-8583-1-ND; Manufactured by: Kemet; Note: DNI; Part Description: CAP CER 5PF 100V NP0 0402; Part Number: CBR04C509B1GAC
C42 C43 C48 C49 = Capacitor_3: Distributed by: Digikey; Distributor Part #: 712-1276-1-ND; Manufactured by: Johanson Technology Inc; Note: DNI; Part Description: CAP CER 27PF 50V 2% NP0 0402; Part Number: 500R07S270GV4T
L5 L8 L9 L12 = INDUCTOR: Distributed by: Coilcraft; Distributor Part #: 0402HP-13NXGLU; Manufactured By: Coilcraft; Note: DNI; Part Description: Chip Inductors – 0402HP; Part Number: 0402HP-13NXGLU; size: 0402
L6 L7 L10 L11 = INDUCTOR: Distributed by: Coilcraft; Distributor Part #: 0603CS-68NXGLU; Manufactured By: Coilcraft; Note: DNI; Part Description: Chip Inductors – 0603CS; Part Number: 0603CS-68NXGLU; size: 0603
FMC = ASP-134488-01_0: Comment: FMCA, FMCB, FMCC, FMCD and FMCE are only one part so Quantity should only be 1; Distributed by: Digikey; Distributor Part #: SAM8730-ND; Manufactured by: Samtec Inc; Part Description: CONN SNGL-END ARRAY MALE 400POS; Part Number: SEAM-40-02.0-S-10-2-A-K-TR
Q4 = BSS138_SOT: Distributed by: Digikey; Distributor Part #: SSM3K37MFVL3FCT-ND; Manufactured by: Toshiba; Part Description: MOSFET N-CH 20V 250MA VESM
R60 R61 R67 R121-R125 R159 = Resistor_3: Distributed by: Digikey; Distributor Part #: 541-10.0KLCT-ND; Manufactured by: Vishay Dale; Part Description: RES 10.0K OHM 1/16W 1% 0402 SMD; Part Number: CRCW040210K0FKED
R68 = Resistor_3: Distributed by: Digikey; Distributor Part #: P56JCT-ND; Manufactured by: Panasonic - ECG; Part Description: RES 56 OHM 1/10W 5% 0402 SMD; Part Number: ERJ-2GEJ560X
R69 R119 R120 = Resistor_3: Distributed by: Digikey; Distributor Part #: P0.0GCT-ND; Manufactured by: Panasonic Electronic Components; Part Description: RES 0.0 OHM 1/10W 0603 SMD; Part Number: ERJ-3GEY0R00V
SYNC = LED: Green LED; Distributed by: Digikey; Distributor Part #: 160-1414-1-ND; Manufactured by: LITEON; Manufaturer: LITEON; Mfr Prt #: LTST-C170KGKT; Mfr_Name: Liteon; Mfr_Part_Number: LTST-C170KGKT; Package: SMD; Part Description: LED GREEN CLEAR 0805 SMD; Part Number: LTST-C170KGKT; Terasic_Prt: M0200
R70 = Resistor_3: Distributed by: Digikey; Distributor Part #: P33.0LCT-ND; MFR's P/N: ERJ-2RKF33R0X; Manufactured by: Panasonic - ECG; Note: DNI; Part Description: RES 100.0 OHM 1/10W 1% 0402 SMD; Part Number: ERJ-2RKF1000X
R71 = Resistor_3: Distributed by: Digikey; Distributor Part #: P33.0LCT-ND; MFR's P/N: ERJ-2RKF33R0X; Manufactured by: Panasonic - ECG; Part Description: RES100.0 OHM 1/10W 1% 0402 SMD; Part Number: ERJ-2RKF1000X
R217 R218 = Resistor_3: Distributed by: Digikey; Distributor Part #: P100ABCT-ND; Manufactured by: Panasonic Electronic Components; Part Description: RES 100 OHM 1/20W 1% 0201 SMD; Part Number: ERJ-2RKF3000X
R219 = Resistor_3: Distributed by: Digikey; Distributor Part #: P100ABCT-ND; Manufactured by: Panasonic Electronic Components; Part Description: RES 100 OHM 1/20W 1% 0201 SMD; Part Number: ERJ-2RKF75R0X
R220 R221 = Resistor_3: Distributed by: Digikey; Distributor Part #: 311-0.0JRCT-ND; MFR's P/N: RC0402JR-070RL; Manufactured by: Yageo; Part Description: RES 0.0 OHM 1/16W 0402 SMD; Part Number: RC0402JR-070RL
C182 C207 C209 C217 C226 C228 C236 C238 C240 C242 = Capacitor_4: Distributed by: Digikey; Distributor Part #: 478-1239-1-ND; Manufactured by: AVX Corporation; Part Description: CAP CERM .1UF 10% 16V X7R 0603; Part Number: 0603YC104KAT2A
C183 C184 C203 C213 C222 C232 = Cap_1: Distributed by: Digikey; Distributor Part #: 445-1260-1-ND; Manufactured by: TDK Corporation; Part Description: CAP CER 10000PF 25V 10% X7R 0402; Part Number: C1005X7R1E103K050BB
C185 C186 = Cap_1: Distributed by: Digikey; Distributor Part #: 490-1287-1-ND; Manufactured by: Murata Electronics North America; Part Description: CAP CER 47PF 50V 5% NP0 0402; Part Number: GRM1535C1H470JDD5D
C190-C195 = Capacitor_0: Distributed by: Digikey; Distributor Part #: 490-5415-1-ND; Manufactured by: Murata Electronics North America; Part Description: CAP CER 0.1UF 16V 10% X5R 0402; Part Number: GRM155R61C104KA88D
JP1 = Jumper_1x3_100_0: Mfr_Name: SAMTEC; Mfr_Part_Number: HMTSW-103-07-G-S-.230; Note: (SHUNT 1-2); TI_Silktext: TXENABLE
JP2 = HDR-1x2_0: Distributed by: Digikey; Distributor Part #: SAM1029-02-ND; Manufactured by: Samtec Inc; Part Description: CONN HEADER 2POS .100" SGL GOLD; Part Number: TSW-102-07-G-S
LMKSPI = HDR-2x5: Distributed by: Digikey; Distributor Part #: SAM1028-05-ND; Manufactured by: Samtec Inc; Note: DNI; Part Description: CONN HEADER 10POS .100" DL GOLD; Part Number: TSW-105-07-G-D
R126-R144 = Resistor_3: Distributed by: Digikey; Distributor Part #: P22.0LCT-ND; MFR's P/N: RC0402JR-070RL; Manufactured by: Panasonic Electronic Components; Part Description: RES 22.0 OHM 1/10W 1% 0402 SMD; Part Number: ERJ-2RKF22R0X
R146 R148 R150 R153 R155 = Resistor_0: Distributed by: Digikey; Distributor Part #: 541-24KJCT-ND; Manufactured by: Vishay Dale; Note: DNI; Part Description: RES 24K OHM 1/16W 5% 0402 SMD; Part Number: CRCW040224K0JNED
R147 R149 R151 R152 R156 = Resistor_0: Distributed by: Digikey; Distributor Part #: P15.0KLCT-ND; Manufactured by: Panasonic Electronic Components; Note: DNI; Part Description: RES 15K OHM 1/10W 1% 0402 SMD; Part Number: ERJ-2RKF1502X
U6 = FT245RL: Distributed by: Digikey; Distributor Part #: 768-1011-1-ND; Manufactured by: FTDI, Future Technology Devices International Ltd; Part Description: IC USB TO PARALLEL FIFO 28-SSOP; Part Number: FT245RL-REEL
U7 = LP5900SD-??_1: Distributed by: Digikey; Distributor Part #: LP5900SD-1.8CT-ND; Manufactured by: National Semiconductor; Part Description: IC REG LDO 1.8V .15A 6-LLP
U14-U16 = SN74AVC4T774: Distributed by: Digikey; Distributor Part #: 296-24739-1-ND; Manufactured by: Texas Instruments; Part Description: IC BUS TRANSCVR 4BIT DL 16TSSOP; Part Number: SN74AVC4T774PWR
USB = USB_MINI_AB_MNE20-5G5P10: Distributed by: Digikey; Distributor Part #: 670-1523-1-ND; Manufactured by: Wurth Electronics Inc; Part Description: CONN RCPT USB MINI AB R/A SMT; Part Number: 651305142821; TI_SILKTEXT: 5V_USB
V_VCXO3p3 V_XO3P3 VA3.0_LED VAMP VLMK3p3 VSPI1.8 = HDR-1x1_2: Manufactured by: Keystone; Note: DNI; Part Number: 5005
Z1-Z4 Z6 Z7 Z9 Z11-Z14 Z17 = NFM41_0: Distributed by: Digikey; Distributor Part #: 490-2550-1-ND; Manufactured by: Murata Electronics North America; Part Description: FILTER LC HIGH FREQ .2UF 1806; Part Number: NFM41PC204F1H3L
Z_SH-H12 = SHUNT-HEADER
+4V = Terminal_Block4_0: Distributed by: Digikey; Distributor Part #: 277-1095-ND; Manufactured by: Phoenix Contact; Part Description: CONN HEADER RT ANG 2POS 5.08MM; Part Number: 1759017
+4V_POWER_CONNECTOR +5V_POWER_CONNECTOR = MechPart: Distributed by: Digi Key; Distributor Part #: 277-1011-ND; Manufactured by: Phoenix Contact; Part Description: CONN TERM BLOCK PLUG 2POS 5.08MM; Part Number: 1757019
+5V = Terminal_Block4_30: Distributed by: Digikey; Distributor Part #: 277-1095-ND; Manufactured by: Phoenix Contact; Note: DNI; Part Description: CONN HEADER RT ANG 2POS 5.08MM; Part Number: 1759017
C201 C206 C208 C211 C216 C220 C225 C227 C230 C235 C237 C239 C241 = Cap_Polar_1: Distributed by: Digikey; Distributor Part #: 478-3859-1-ND; MFR's P/N: TAJA106M016RNJ; Manufactured by: AVX Corporation; Part Description: CAP TANTALUM 10UF 16V 20% SMD; Part Number: TAJA106M016RNJ
C202 C212 C221 C231 = Capacitor_0: Distributed by: Digikey; Distributor Part #: 399-1254-1-ND; MFR's P/N: C1206C105K4RACTU; Manufactured by: Kemet; Part Description: CAP 1.0UF 16V CERAMIC X7R 1206; Part Number: C1206C105K4RACTU
C205 C215 C224 C233 = Capacitor_3: Distributed by: Digikey; Distributor Part #: 445-1309-1-ND; MFR's P/N: C1608X7R1H222K; Manufactured by: TDK Corporation; Part Description: CAP CER 2200PF 50V X7R 10% 0603; Part Number: CGA3E2X7R1H222K080AA
C210 = Cap_1: Distributed by: Digikey; Distributor Part #: 490-5415-1-ND; Manufactured by: TDK; Part Description: CAP CER 1UF 16V 10% X5R 0402; Part Number: C1005X5R1C105K050BC
GND GND1 GND1.2 GND1.8 GND2 GND3.0 = HDR-1x1_2: Manufactured by: Keystone; Part Number: 5006
MT1-MT6 = TEST_POINT: TESTPOINT; Distributor: N/A; Distributor Part Number: N/A; Manufacturer: N/A; Manufacturer Part Number: N/A; Part Description: DO NOT POPULATE
R160 R168 R175 = Resistor_0: Distributed by: Digikey; Distributor Part #: P1.00KLCT-ND; Manufactured by: Panasonic - ECG; Part Description: RES 1.00K OHM 1/10W 1% 0402 SMD; Part Number: ERJ-2RKF1001X
R161 R165 R179-R181 R235 R236 = Resistor_0: Note: DNI
R162 = Resistor_0: Distributed by: Digikey; Distributor Part #: 541-200LCT-ND; Manufactured by: Vishay Dale; Part Description: RES 200 OHM 1/16W 1% 0402 SMD; Part Number: CRCW0402200RFKED
R163 R167 R171 R178 = Resistor_0: Distributed by: Digikey; Distributor Part #: P1.00KLCT-ND; MFR's P/N: ERJ-2RKF1001X; Manufactured by: Panasonic - ECG; Part Description: RES 1.00K OHM 1/10W 1% 0402 SMD; Part Number: ERJ-2RKF1001X
R164 = Resistor_0: Distributed by: Digikey; Distributor Part #: P1.00KLCT-ND; Manufactured by: Vishay Dale; Part Description: RES 10.0K OHM 1/16W 1% 0402 SMD; Part Number: CRCW040210K0FKED
R166 = Resistor_0: Distributed by: Digikey; Distributor Part #: P806LCT-ND; MFR's P/N: ERJ-2RKF8060X; Manufactured by: Panasonic - ECG; Part Description: RES 806 OHM 1/10W 1% 0402 SMD; Part Number: ERJ-2RKF8060X
R170 = Resistor_0: Distributed by: Digikey; Distributor Part #: 541-2.10KLCT-ND; Manufactured by: Vishay Dale; Part Description: RES 2.10K OHM 1/16W 1% 0402 SMD; Part Number: CRCW04022K10FKED
R177 = Resistor_0: Distributed by: Digikey; Distributor Part #: 541-2.32KLCT-ND; Manufactured by: Vishay Dale; Part Description: RES 2.32K OHM 1/16W 1% 0402 SMD; Part Number: CRCW04022K32FKED
SCREW1-SCREW4 = MechPart: Distributed by: Digi Key; Distributor Part #: H782-ND; Manufactured by: BUILDING FASTENERS; Note: MP2; Part Description: SCREW, PHIL, 4-40x3/4", SS; Part Number: PMSSS 440 0075 PH
STANDOFF1-STANDOFF4 = MechPart: Distributed by: Digi Key; Distributor Part #: 2205K-ND; Manufactured by: Keystone Electronics; Note: MP3; Part Description: HEX STANDOFF 4-40 ALUMINUM 1"; Part Number: 2205
U8-U11 = LP3878MR-ADJ_1: IC VREG 800MA ADJ 8-LLP; Distributed by: Digikey; Distributor Part #: LP3878SD-ADJCT-ND; Distributor Part Number: LP3878SD-ADJCT-ND; Manufactured by: National Semiconductor; Manufacturer: National Semiconductor; Manufacturer Part Number: LP3878SD-ADJ/NOPB; Part Description: IC VREG 800MA ADJ 8-LLP; Source: Digikey
VA1p2 VA1p8 VA3.0 VD1p2 = HDR-1x1_2: Manufactured by: Keystone; Part Number: 5005

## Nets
+4V: +4V.1(4V) C201.1 C202.1 C211.1 C212.1 C220.1 C221.1 C230.1 C231.1 R168.1 R175.1 R179.2 R180.2 R181.1 R235.1 R236.1 U8.4(IN) U9.4(IN) U10.4(IN) U11.4(IN)
GND: +4V.2(GND) +5V.2(GND) C3.2 C6.2 C7.2 C8.2 C9.2 C10.2 C11.2 C12.2 C13.2 C14.1 C15.2 C16.1 C24.1 C25.2 C26.1 C27.2 C44.2 C45.1 C50.2 C51.1 C120.1 C121.1 C190.1 C191.1 C192.1 C193.1 C194.1 C195.1 C200.1 C201.2 C202.2 C203.2 C204.2 C206.2 C207.2 C208.2 C209.2 C210.1 C211.2 C212.2 C213.2 C214.2 C216.2 C217.2 C220.2 C221.2 C222.2 C223.2 C225.2 C226.2 C227.2 C228.2 C230.2 C231.2 C232.2 C234.2 C235.2 C236.2 C237.2 C238.2 C239.2 C240.2 C241.2 C242.2 CLK.2(SHIELD2) CLK.3(SHIELD3) CLK.4(SHIELD4) CLK.5(SHIELD5) FMC.A1 FMC.A4 FMC.A5 FMC.A8 FMC.A9 FMC.A12 FMC.A13 FMC.A16 FMC.A17 FMC.A20 FMC.A21 FMC.A24 FMC.A25 FMC.A28 FMC.A29 FMC.A32 FMC.A33 FMC.A36 FMC.A37 FMC.A40 FMC.B2 FMC.B3 FMC.B6 FMC.B7 FMC.B10 FMC.B11 FMC.B14 FMC.B15 FMC.B18 FMC.B19 FMC.B22 FMC.B23 FMC.B26 FMC.B27 FMC.B30 FMC.B31 FMC.B34 FMC.B35 FMC.B38 FMC.B39 FMC.C1 FMC.C4 FMC.C5 FMC.C8 FMC.C9 FMC.C12 FMC.C13 FMC.C16 FMC.C17 FMC.C20 FMC.C21 FMC.C24 FMC.C25 FMC.C28 FMC.C29 FMC.C32 FMC.C33 FMC.C36 FMC.C38 FMC.C40 FMC.D2 FMC.D3 FMC.D6 FMC.D7 FMC.D10 FMC.D13 FMC.D16 FMC.D19 FMC.D22 FMC.D25 FMC.D28 FMC.D37 FMC.D39 FMC.E1 FMC.E4 FMC.E5 FMC.E8 FMC.E11 FMC.E14 FMC.E17 FMC.E20 FMC.E23 FMC.E26 FMC.E29 FMC.E32 FMC.E35 FMC.E38 FMC.E40 FMC.F2 FMC.F3 FMC.F6 FMC.F9 FMC.F12 FMC.F15 FMC.F18 FMC.F21 FMC.F24 FMC.F27 FMC.F30 FMC.F33 FMC.F36 FMC.F39 FMC.G1 FMC.G4 FMC.G5 FMC.G8 FMC.G11 FMC.G14 FMC.G17 FMC.G20 FMC.G23 FMC.G26 FMC.G29 FMC.G32 FMC.G35 FMC.G38 FMC.G40 FMC.H2 FMC.H3 FMC.H6 FMC.H9 FMC.H12 FMC.H15 FMC.H18 FMC.H21 FMC.H24 FMC.H27 FMC.H30 FMC.H33 FMC.H36 FMC.H39 FMC.J1 FMC.J4 FMC.J5 FMC.J8 FMC.J11 FMC.J14 FMC.J17 FMC.J20 FMC.J23 FMC.J26 FMC.J29 FMC.J32 FMC.J35 FMC.J38 FMC.J40 FMC.K2 FMC.K3 FMC.K6 FMC.K9 FMC.K12 FMC.K15 FMC.K18 FMC.K21 FMC.K24 FMC.K27 FMC.K30 FMC.K33 FMC.K36 FMC.K39 GND.1 GND1.1 GND1.2.1 GND1.8.1 GND3.0.1 L1.2 L2.2 L3.1 L4.1 Q4.2(S) R1.1 R2.2 R4.1 R5.1 R31.2 R32.2 R34.1 R35.1 R40.1 R60.2 R67.2 R70.2 R71.2 R125.1 R145.2 R146.2 R148.2 R150.2 R153.2 R155.2 R159.2 R161.1 R163.2 R165.1 R167.2 R169.2 R171.2 R176.2 R178.2 R217.1 R218.1 SYSREF.2(SHIELD2) SYSREF.3(SHIELD3) SYSREF.4(SHIELD4) SYSREF.5(SHIELD5) T3.4 T4.4 T8.2 T8.4 T9.2 T9.6 U3.3(A5/GND) U3.6(B5/GND) U3.7(B4/GND/UPB) U3.8(B3/GND/DNB) U3.9(B2/GND/S1B) U3.10(B1/GND/S0B) U3.13(GND) U3.15(GND) U3.16(B0/GND) U3.20(LATB/GND) U3.21(LATA/GND) U3.25(A0/GND) U3.26(GND) U3.28(GND) U3.DAP U8.3(GND) U8.DAP U9.3(GND) U9.DAP U10.3(GND) U10.DAP U11.3(GND) U11.DAP U14.1(DIR1) U14.2(DIR2) U14.7(DIR3) U14.9(OEb) U14.10(GND) U15.1(DIR1) U15.2(DIR2) U15.7(DIR3) U15.8(DIR4) U15.9(OEb) U15.10(GND) U15.11(B4) U16.1(DIR1) U16.2(DIR2) U16.8(DIR4) U16.10(GND) VINA+.2(SHIELD2) VINA+.3(SHIELD3) VINA+.4(SHIELD4) VINA+.5(SHIELD5) VINA-.2(SHIELD2) VINA-.3(SHIELD3) VINA-.4(SHIELD4) VINA-.5(SHIELD5) VINB+.2(SHIELD2) VINB+.3(SHIELD3) VINB+.4(SHIELD4) VINB+.5(SHIELD5) VINB-.2(SHIELD2) VINB-.3(SHIELD3) VINB-.4(SHIELD4) VINB-.5(SHIELD5) Z2.2 Z2.3 Z4.2 Z6.2 Z7.2 Z9.2 Z11.2 Z12.2 Z13.2 Z14.2 Z17.2 ; also on sheet 8 9
GND2: C180.2 C181.2 C182.2 C183.2 C184.2 C185.2 C186.2 C187.2 GND2.1 U6.7(GND) U6.18(GND) U6.21(GND) U6.25(AGND) U6.26(TEST) U7.3(GND) U7.7(DAP) USB.5(GND) USB.6(GND1) USB.7(GND2) USB.8(GND3) USB.9(GND4) Z1.2 Z2.1 Z3.2
ADC_VCMA: R16.2 ; also on sheet 9
ADC_VCMB: R27.2 ; also on sheet 9
ADC_VINA+: R12.1 ; also on sheet 9
ADC_VINA-: R13.1 ; also on sheet 9
ADC_VINB+: R25.1 ; also on sheet 9
ADC_VINB-: R24.1 ; also on sheet 9
CLK_VIN+: R72.2 R74.2 R76.2 ; also on sheet 9
CLK_VIN-: R73.2 R75.2 R77.2 ; also on sheet 9
CSb_ADC: R122.1 R128.2 U14.13(B2)
CSb_ADC_3p0: R66.2 R135.2 ; also on sheet 9
CSb_LMH: R123.1 R129.2 U15.13(B2)
CSb_LMH_3p3: J1.2 R139.2 U3.32(A2/CS/S1A)
CSb_LMK: R124.1 R130.2 U16.13(B2)
CSb_LMK_3p3: R142.2 R146.1 R147.1 ; also on sheet 8
DIR_LMK: R125.2 R133.2 U16.11(B4)
EXT_ ADC_CLK: R218.2 R219.1 ; also on sheet 8
FILT_VINA+: C16.2 C31.1 C47.2 C48.2 L9.1
FILT_VINA-: C15.1 C30.1 C46.2 C48.1 L9.2
FILT_VINB+: C13.1 C28.1 C40.2 C42.1 L5.2
FILT_VINB-: C14.2 C29.1 C41.2 C42.2 L5.1
FILT_VOUTA+: C49.2 C51.2 L11.2 L12.1 R14.2
FILT_VOUTA-: C49.1 C50.1 L10.2 L12.2 R15.2
FILT_VOUTB+: C43.1 C44.1 L6.2 L8.2 R29.1
FILT_VOUTB-: C43.2 C45.2 L7.2 L8.1 R28.1
FMC_ADC_DEVCLK+: FMC.D8 R76.1
FMC_ADC_DEVCLK-: FMC.D9 R77.1
FMC_ADC_SYSREF+: FMC.D11 R83.1
FMC_ADC_SYSREF-: FMC.D12 R82.1
FMC_FPGA_DEVCLKA+: FMC.D4 ; also on sheet 8
FMC_FPGA_DEVCLKA-: FMC.D5 ; also on sheet 8
FMC_FPGA_DEVCLKB+: FMC.G6 ; also on sheet 8
FMC_FPGA_DEVCLKB-: FMC.G7 ; also on sheet 8
FMC_FPGA_SYSREF+: FMC.G9 ; also on sheet 8
FMC_FPGA_SYSREF-: FMC.G10 ; also on sheet 8
INA+: R8.2 T2.1
INA-: R9.2 T2.3
INB+: R21.2 T6.3
INB-: R20.2 T6.1
LMH_VINA: R3.2 T8.6
LMH_VINB: R6.1 T9.4
LMK_ADC_DEVCLK+: R74.1 ; also on sheet 8
LMK_ADC_DEVCLK-: R75.1 ; also on sheet 8
LMK_ADC_SYSREF+: R81.1 ; also on sheet 8
LMK_ADC_SYSREF-: R80.1 ; also on sheet 8
LMK_DIR: R144.2 U16.7(DIR3)
OVRA/TRIGRDY: FMC.G27 ; also on sheet 9
OVRB/TRIGGER: FMC.D26 ; also on sheet 9
PG_C2M: FMC.D1 R60.1
PG_M2C: FMC.F1 R61.1
RESET_LMK_3p3: R152.2 R153.1 ; also on sheet 8
SA0+: FMC.A3 ; also on sheet 9
SA0-: FMC.A2 ; also on sheet 9
SA1+: FMC.C7 ; also on sheet 9
SA1-: FMC.C6 ; also on sheet 9
SB0+: FMC.A11 ; also on sheet 9
SB0-: FMC.A10 ; also on sheet 9
SB1+: FMC.A7 ; also on sheet 9
SB1-: FMC.A6 ; also on sheet 9
SCLK_ADC_3p0: R65.2 R134.2 ; also on sheet 9
SCLK_ADC_LMH_LMK: R126.2 U14.14(B1) U15.14(B1) U16.14(B1)
SCLK_LMH_3p3: J1.1 R138.2 U3.2(A4/CLK/UPA)
SCLK_LMK_3p3: R141.2 R150.1 R151.1 ; also on sheet 8
SDI_ADC_3p0: R63.1 R136.2 ; also on sheet 9
SDI_ADC_LMH: R127.2 U14.12(B3) U15.12(B3)
SDI_LMH_3p3: J1.3 R140.2 U3.1(A3/SDI/DNA)
SDIO_LMK: R132.2 U16.12(B3)
SDIO_LMK_3p3: R143.2 R148.1 R149.1 ; also on sheet 8
SDO_ADC: R131.2 U14.11(B4)
SDO_ADC_3p0: R64.1 R137.2 ; also on sheet 9
SYNC_LMK_3p3: R155.1 R156.2 ; also on sheet 8
SYNCb+: FMC.G12 ; also on sheet 9
SYNCb-: FMC.G13 ; also on sheet 9
SYSREF_VIN+: R78.2 R81.2 R83.2 ; also on sheet 9
SYSREF_VIN-: R79.2 R80.2 R82.2 ; also on sheet 9
V_VCXO3.3: C239.1 C240.1 V_VCXO3p3.1 Z13.3 ; also on sheet 8
V_XO3.3: C237.1 C238.1 V_XO3P3.1 Z12.3 ; also on sheet 8
VA1.2: C206.1 C207.1 VA1p2.1 Z4.3 ; also on sheet 9
VA1.8: C216.1 C217.1 VA1p8.1 Z7.3 ; also on sheet 9
VA3.0: C225.1 C226.1 R160.1 R164.1 VA3.0.1 Z9.3 ; also on sheet 9
VA3.0_LED: C227.1 C228.1 JP1.1(Pin1) R68.1 U14.8(DIR4) VA3.0_LED.1 Z14.3 ; also on sheet 9
VADJ: FMC.E39 FMC.F40 FMC.G39 FMC.H40 R61.2 R69.1
VAMP: C24.2 C25.1 C26.2 C27.1 C241.1 C242.1 R30.2 R33.2 U3.14(+5V) U3.27(+5V) VAMP.1 Z17.3
VD1.2: C208.1 C209.1 VD1p2.1 Z6.3 ; also on sheet 9
VIO_B_M2C: FMC.J39 FMC.K40 R69.2
VLMK3.3: C191.2 C193.2 C235.1 C236.1 R17.1 U15.16(VCCA) U16.16(VCCA) VLMK3p3.1 Z11.3 ; also on sheet 8
VSPI1.8: C182.1 C184.1 C190.2 C192.2 C194.2 JP1.3(Pin3) JP2.1 R121.2 R122.2 R123.2 R124.2 U6.4(VCCIO) U14.15(VCCB) U15.15(VCCB) U16.15(VCCB) VSPI1.8.1 Z3.3
N17161280: C223.1 C224.1 R170.2 R179.1 U10.5(OUT) Z9.1 Z14.1
N17161345: C224.2 R170.1 R171.1 U10.6(ADJ)
N17161357: C222.1 U10.1(BYPASS)
N17161563: C233.1 C234.1 R177.2 R180.1 U11.5(OUT) Z11.1 Z12.1 Z13.1
N17161629: R175.2 R176.1 U11.8(~{SD})
N17161669: C233.2 R177.1 R178.1 U11.6(ADJ)
N17161679: C232.1 U11.1(BYPASS)
N17161879: C204.1 C205.1 R162.2 U8.5(OUT) Z4.1 Z6.1
N17161936: C200.2 R160.2 R161.2 R235.2 U8.8(~{SD})
N17162041: C214.1 C215.1 R166.2 U9.5(OUT) Z7.1
N17162051: C210.2 R164.2 R165.2 R236.2 U9.8(~{SD})
N17162120: C215.2 R166.1 R167.1 U9.6(ADJ)
N17162132: C213.1 U9.1(BYPASS)
N17162350: C205.2 R162.1 R163.1 U8.6(ADJ)
N17162360: C203.1 U8.1(BYPASS)
N17167261: LMKSPI.2(E) R147.2
N17167267: LMKSPI.4(F) R149.2
N17167273: LMKSPI.8(H) R151.2
N17243114: FMC.H37 R65.1
N17243121: FMC.H38 R66.1
N17243521: FMC.G36 R63.2
N17243524: FMC.G37 R64.2
N17394464: Q4.3(D) SYNC.2(CATHODE)
N17498929: FMC.H31 Q4.1(G) R67.1
N17500015: FMC.D31 R62.1
N17500071: FMC.D30 R62.2
N17502672: R168.2 R169.1 U10.8(~{SD})
N17588026: L1.1 R36.2 U3.24(OPA+)
N17588195: C21.2 T9.3
N17588197: C20.2 T9.1
N17588243: R34.2 U3.22(ENA)
N17588312: R30.1 R31.1 U3.4(MOD0)
N17588326: R32.1 R33.1 U3.5(MOD1)
N17588682: C21.1 U3.30(IPA+)
N17588716: C20.1 U3.29(IPA-)
N17588832: L2.1 R37.2 U3.23(OPA-)
N17588912: L4.2 R38.2 U3.18(OPB-)
N17589096: C22.1 U3.11(IPB+)
N17589248: C23.1 U3.12(IPB-)
N17589348: R35.2 U3.19(ENB)
N17589483: C23.2 T8.3
N17591143: L3.2 R39.2 U3.17(OPB+)
N17597838: R119.1 R120.2 Z1.3
N17597840: C183.1 R119.2 U6.20(VCC)
N17597844: C180.1 R120.1 U7.4(EN) U7.6(VIN)
N17597872: C181.1 U7.1(VOUT) Z3.1
N17597980: R126.1 U6.1(D0)
N17597982: R127.1 U6.5(D1)
N17597984: R128.1 U6.3(D2)
N17597986: R129.1 U6.11(D3)
N17597988: R130.1 U6.2(D4)
N17597998: R131.1 U6.9(D5)
N17598000: R132.1 U6.10(D6)
N17598002: R133.1 U6.6(D7)
N17599264: C185.1 U6.16(USBDM) USB.2(D-)
N17599267: C186.1 U6.15(USBDP) USB.3(D+)
N17600241: USB.1(VBUS) Z1.1
N17600317: C187.1 U6.17(3V3OUT)
N17600450: R121.1 U6.12(~{PWREN})
N17601684: R134.1 U14.3(A1)
N17602039: R138.1 U15.3(A1)
N17602344: R141.1 U16.3(A1)
N17602346: R142.1 U16.4(A2)
N17602348: R143.1 U16.5(A3)
N17602350: R144.1 U16.6(A4)
N17603643: R135.1 U14.4(A2)
N17603676: R136.1 U14.5(A3)
N17603709: R137.1 U14.6(A4)
N17603775: R139.1 U15.4(A2)
N17603808: R140.1 U15.5(A3)
N17607444: JP2.2 R159.1 U16.9(OEb)
N17608737: J1.4 R17.2 U3.31(A1/SDO/S0A)
N17692169: C2.2 T2.4
N17692215: R2.1 T1.4 VINA-.1(CENTER)
N17692227: C1.1 T1.1
N17692229: C2.1 T1.3
N17692231: R1.2 R3.1 T1.6 VINA+.1(CENTER)
N17692255: R5.2 R6.2 T7.4 VINB+.1(CENTER)
N17692293: C5.2 T6.4
N17692319: C6.1 T7.2
N17692331: C4.2 T6.6
N17692399: C1.2 T2.6
N17692405: C9.1 C10.1 R7.2 R10.2 R11.2 R16.1 VCMA.1
N17692416: R8.1 R10.1 R12.2 R14.1
N17692426: C7.1 R7.1 T2.2
N17692454: R4.2 T7.6 VINB-.1(CENTER)
N17692538: C11.1 C12.1 R22.2 R23.2 R26.2 R27.1 VCMB.1
N17692596: C5.1 T7.3
N17692598: C4.1 T7.1
N17692610: R9.1 R11.1 R13.2 R15.1
N17692612: C8.1 R26.1 T6.2
N17692676: C3.1 T1.2
N17695733: C40.1 L6.1
N17695767: C41.1 L7.1
N17701277: C22.2 T8.1
N17703127: R20.1 R22.1 R24.2 R28.2
N17703165: R21.1 R23.1 R25.2 R29.2
N17704949: C46.1 L10.1
N17704975: C47.1 L11.1
N17708763: R73.1 T3.3
N17708767: R72.1 T3.1
N17709160: R78.1 T4.1
N17709162: R79.1 T4.3
N17709444: CLK.1(CENTER) R70.1 R220.1
N17709615: R71.1 SYSREF.1(CENTER) T4.6
N17746469: C28.2 R36.1
N17746475: C29.2 R37.1
N17746481: C30.2 R38.1
N17746487: C31.2 R39.1
N17748434: +5V.1(5V) R181.2 Z17.1
N17896945: LMKSPI.6(G) R145.1
N17897426: LMKSPI.9(I) R40.2
N17899231: LMKSPI.7(D) R152.1
N17899957: LMKSPI.1(A) R156.1
N17947980: C195.2 JP1.2(Pin2) U14.16(VCCA)
N18004813: R217.2 R219.2 R221.2
N18004844: R220.2 R221.1 T3.6
N18006132: C120.2 T3.2 T3.5
N18006814: C121.2 T4.2 T4.5
N18065358: R68.2 SYNC.1(ANODE)

Not connected (* = marked no-connect by the designer): FMC A14* A15* A18* A19* A22* A23* A26* A27* A30* A31* A34* A35* A38* A39* B1* B4* B5* B8* B9* B12* B13* B16* B17* B20* B21* B24* B25* B28* B29* B32* B33* B36* B37* B40* C2* C3* C10* C11* C14* C15* C18* C19* C22* C23* C26* C27* C30* C31* C34* C35* C37* C39* D14* D15* D17* D18* D20* D21* D23* D24* D27* D29* D32* D33* D34* D35* D36* D38* D40* E2* E3* E6* E7* E9* E10* E12* E13* E15* E16* E18* E19* E21* E22* E24* E25* E27* E28* E30* E31* E33* E34* E36* E37* F4* F5* F7* F8* F10* F11* F13* F14* F16* F17* F19* F20* F22* F23* F25* F26* F28* F29* F31* F32* F34* F35* F37* F38* G2* G3* G15* G16* G18* G19* G21* G22* G24* G25* G28* G30* G31* G33* G34* H1* H4* H5* H7* H8* H10* H11* H13* H14* H16* H17* H19* H20* H22* H23* H25* H26* H28* H29* H32* H34* H35* J2* J3* J6* J7* J9* J10* J12* J13* J15* J16* J18* J19* J21* J22* J24* J25* J27* J28* J30* J31* J33* J34* J36* J37* K1* K4* K5* K7* K8* K10* K11* K13* K14* K16* K17* K19* K20* K22* K23* K25* K26* K28* K29* K31* K32* K34* K35* K37* K38*; LMKSPI 3(B)* 5(C)* 10(J)*; MT1 1; MT2 1; MT3 1; MT4 1; MT5 1; MT6 1; T1 5*; T2 5*; T6 5*; T7 5*; T8 5(n/c)*; T9 5(n/c)*; U6 8(NC)* 13(~{RD})* 14(WR)* 19(~{RESET})* 22(~{TXE})* 23(~{RXF})* 24(NC)* 27(OSCI)* 28(OSCO)*; U7 2(N/C2)* 5(N/C5)*; U8 2(N/C1)* 7(N/C2)*; U9 2(N/C1)* 7(N/C2)*; U10 2(N/C1)* 7(N/C2)*; U11 2(N/C1)* 7(N/C2)*; U15 6(A4)*; USB 4(ID)*

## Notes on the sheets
sheet 3
- R1-R29
  C1-C19
sheet 4
- LMH SPI
- CONSIDER ADDING VERTICAL SMAs
  TO INTERFACE WITH AMPLIFIER EVM
- 1:4 Z Transformer converts
  50 ohm to 200 ohm DVGA input
sheet 5
- R160-C179
  C200-C249
- BOARD MOUNTING HOLES
sheet 6
- R120-R159
  C180-C199
- Note: LMH6521 SPI Reads
  Not Supported on This EVM
sheet 7
- R60-R69
- DP1_M2C_P
- DP1_M2C_N
- PRSNT_M2C_L
- GBTCLK0_M2C_P
- GBTCLK0_M2C_N
- DP2_M2C_N
- DP2_M2C_P
- DP0_M2C_N
- DP0_M2C_P
- LA00_P_CC
- LA01_P_CC
- LA00_N_CC
- LA01_N_CC
- DP3_M2C_P
- LA03_P
- DP3_M2C_N
- LA05_P_CC
- LA03_N
- LA05_N_CC
- LA08_P
- LA08_N
- LA26_P
- LA25_P
- D30/31 short required
  for KC705 board
